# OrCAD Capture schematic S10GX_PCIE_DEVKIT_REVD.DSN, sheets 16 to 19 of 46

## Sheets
16 S10 GX Ground: size C
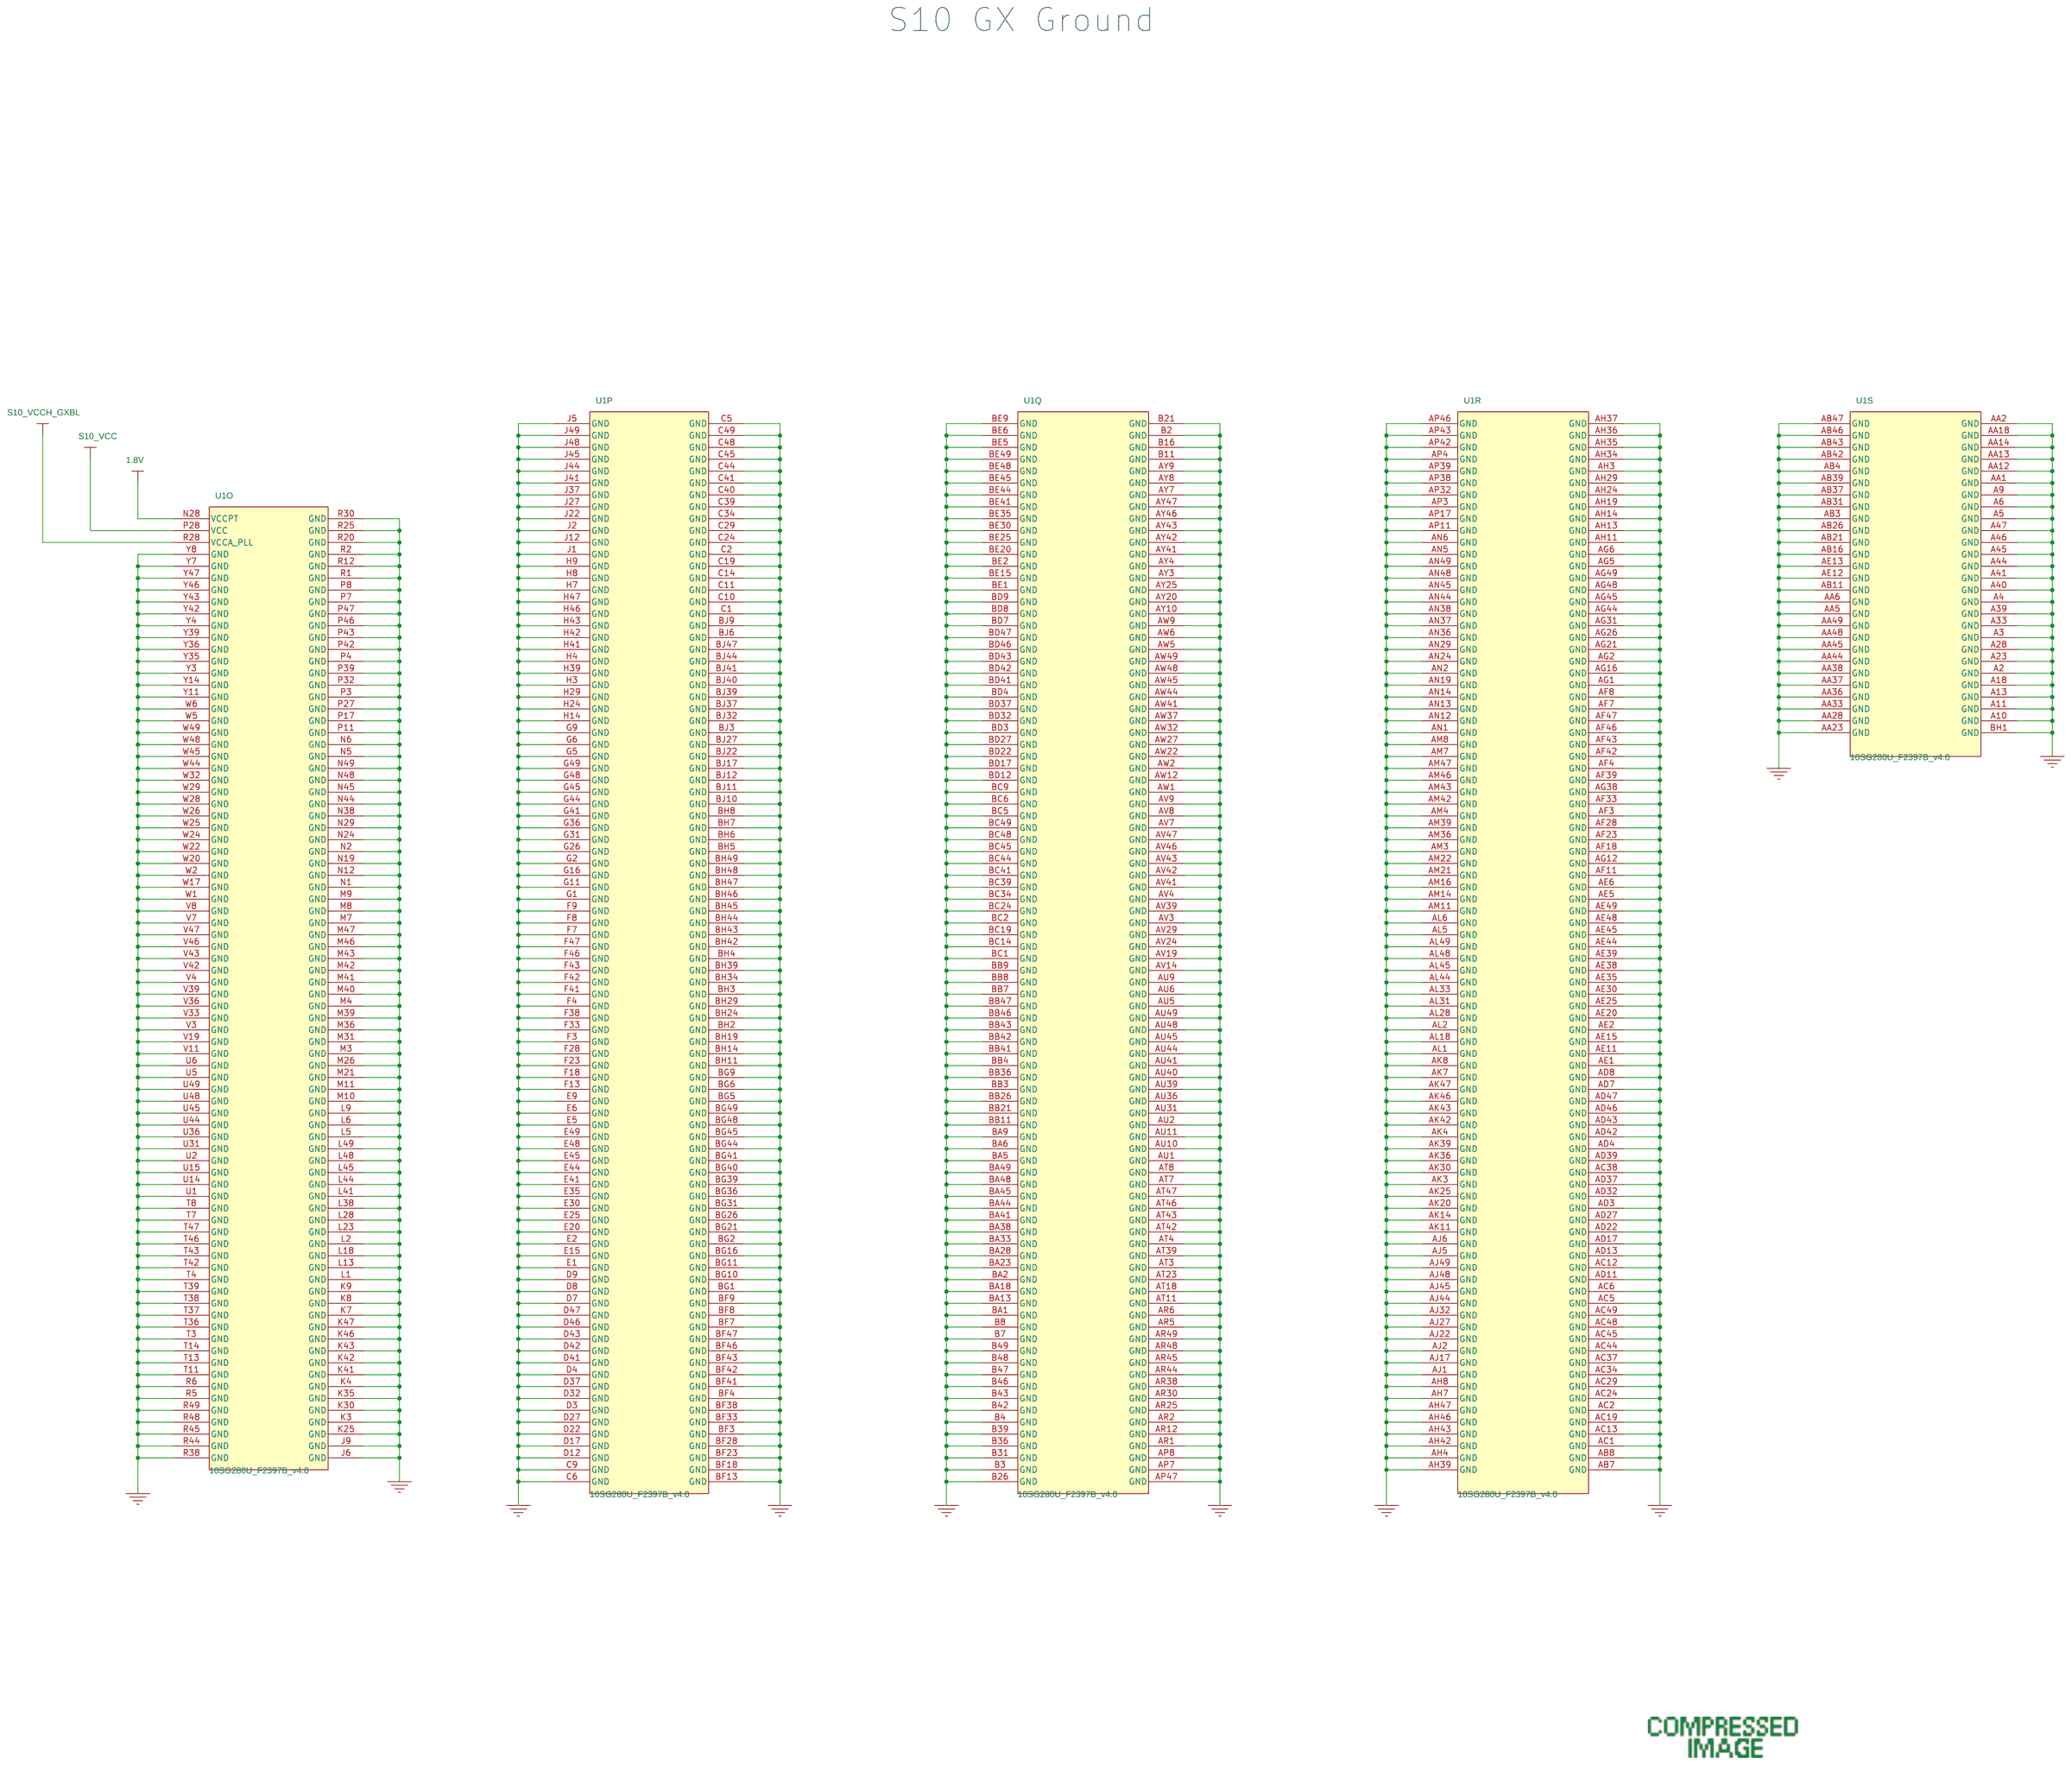
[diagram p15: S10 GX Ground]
17 PCIe Edge Gold Fingers: size C
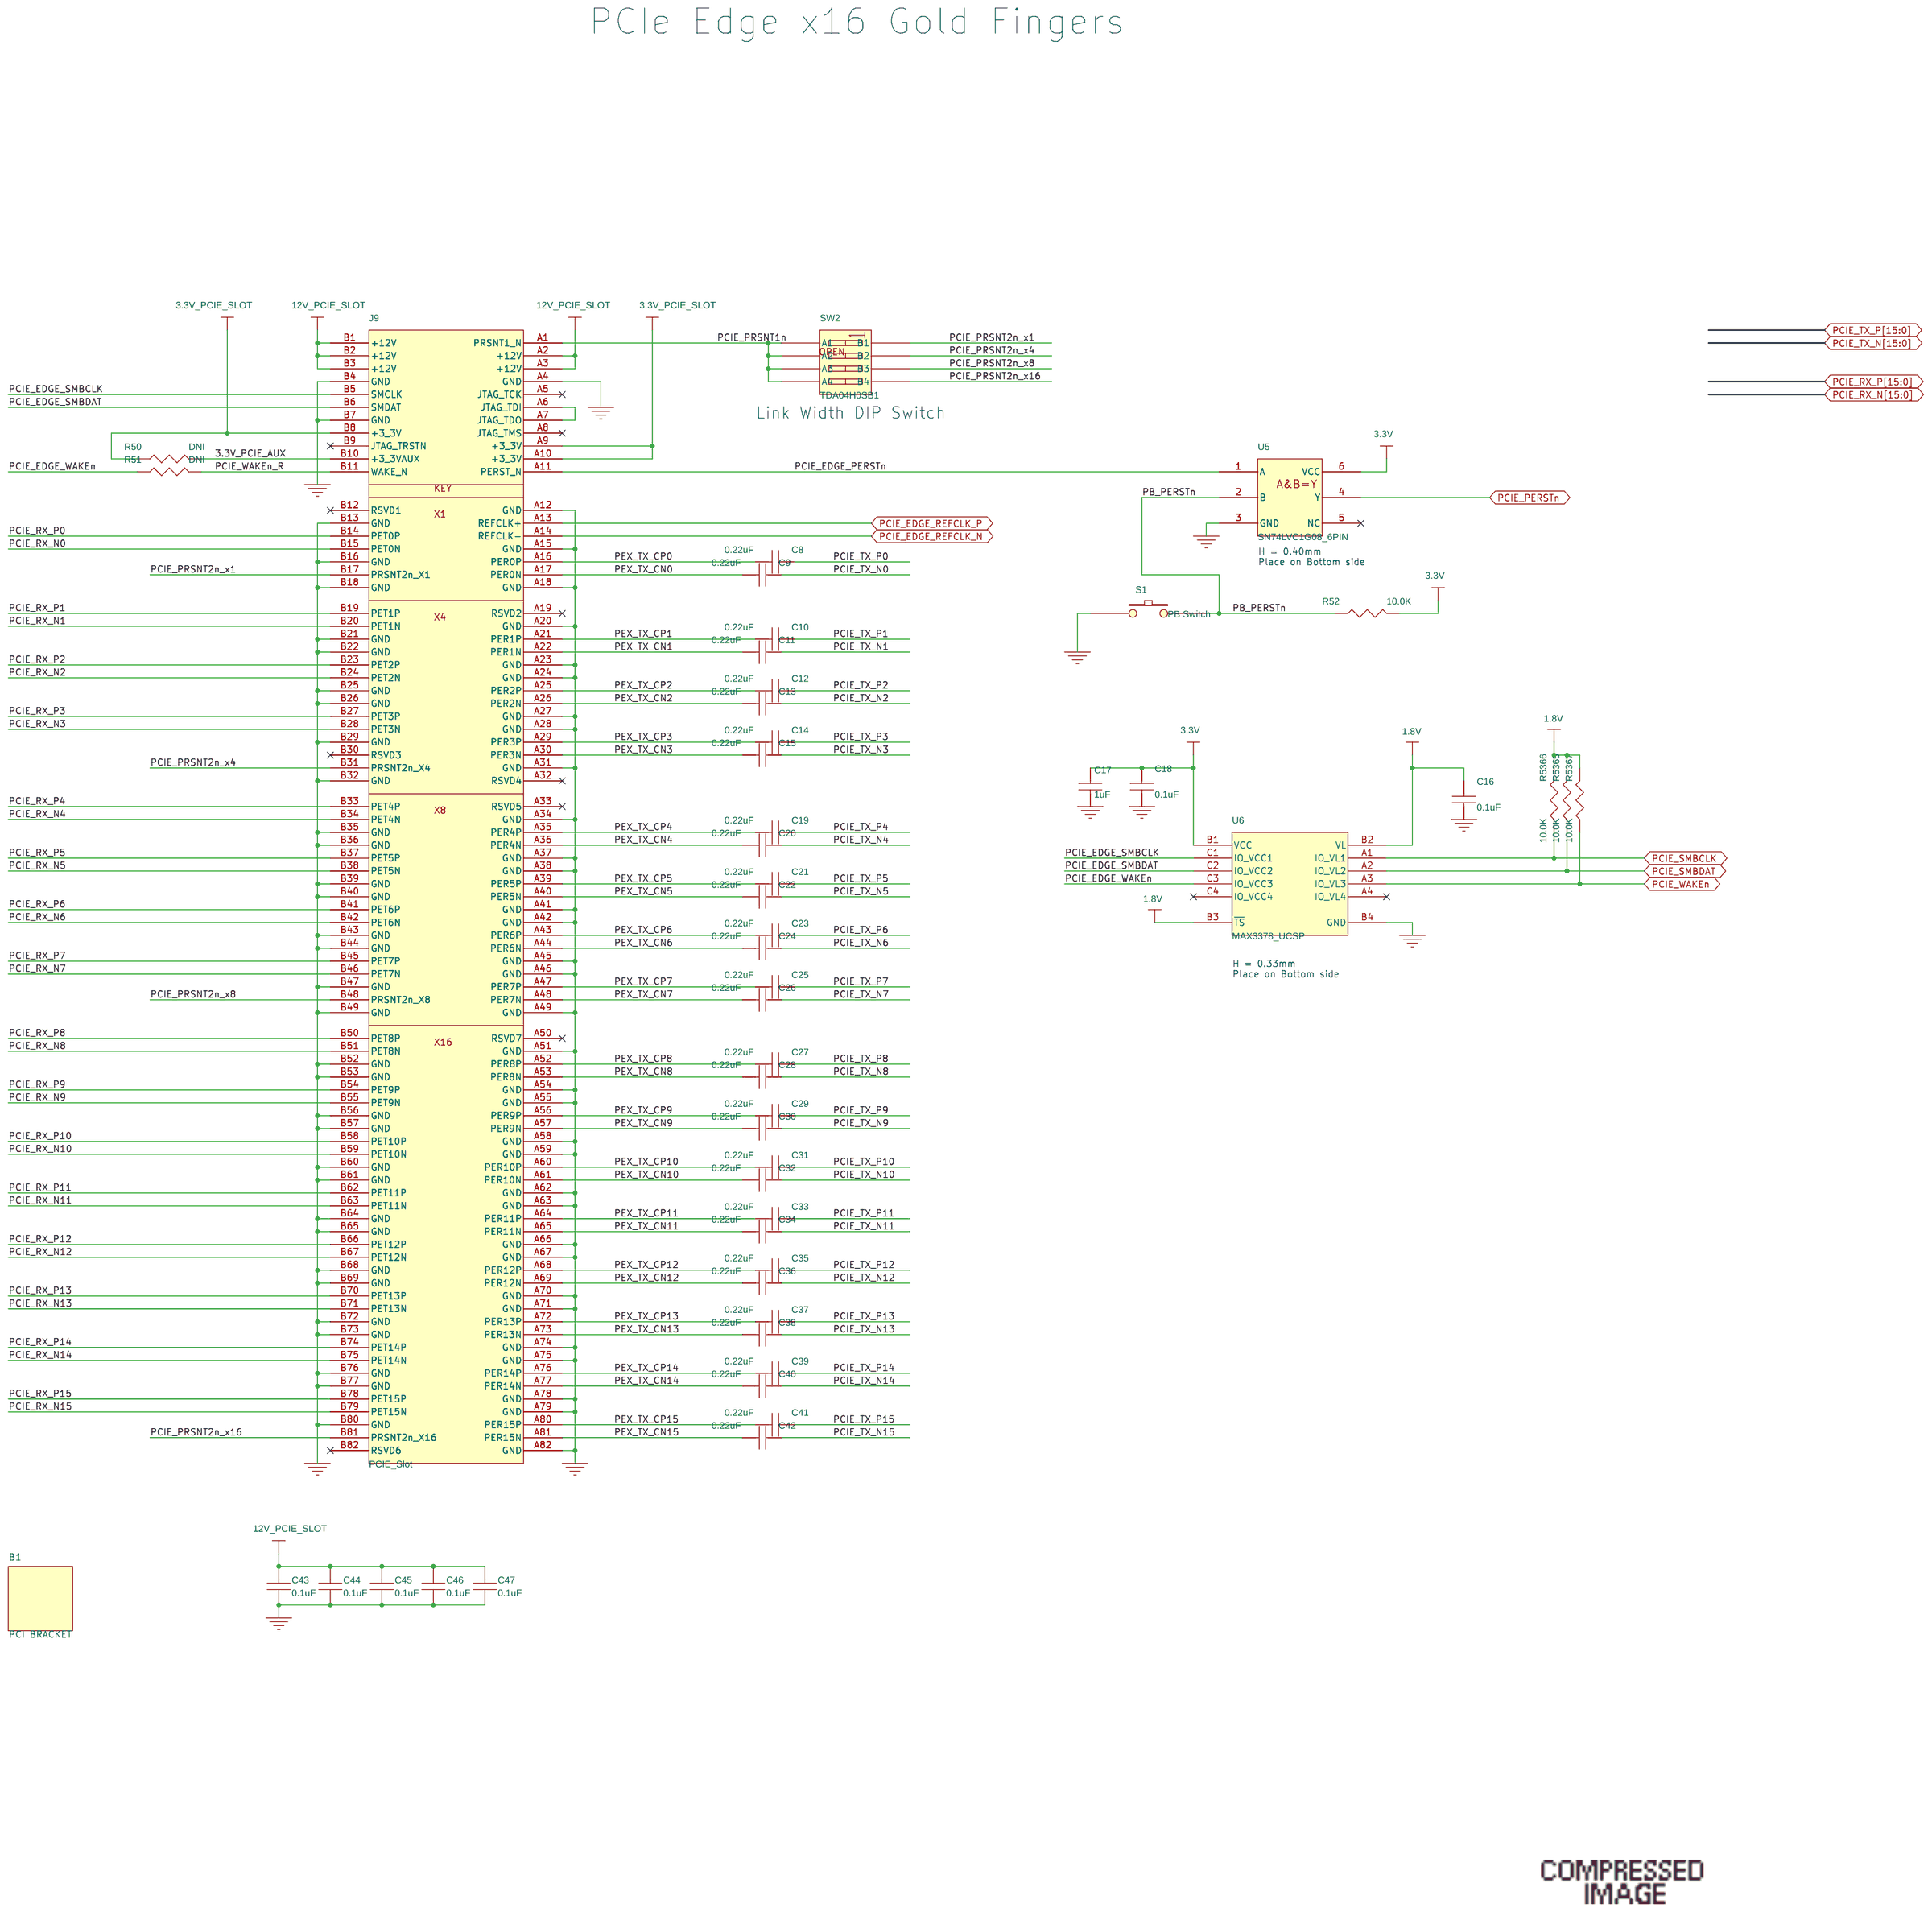
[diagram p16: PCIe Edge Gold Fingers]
18 Board System Clocks: size C
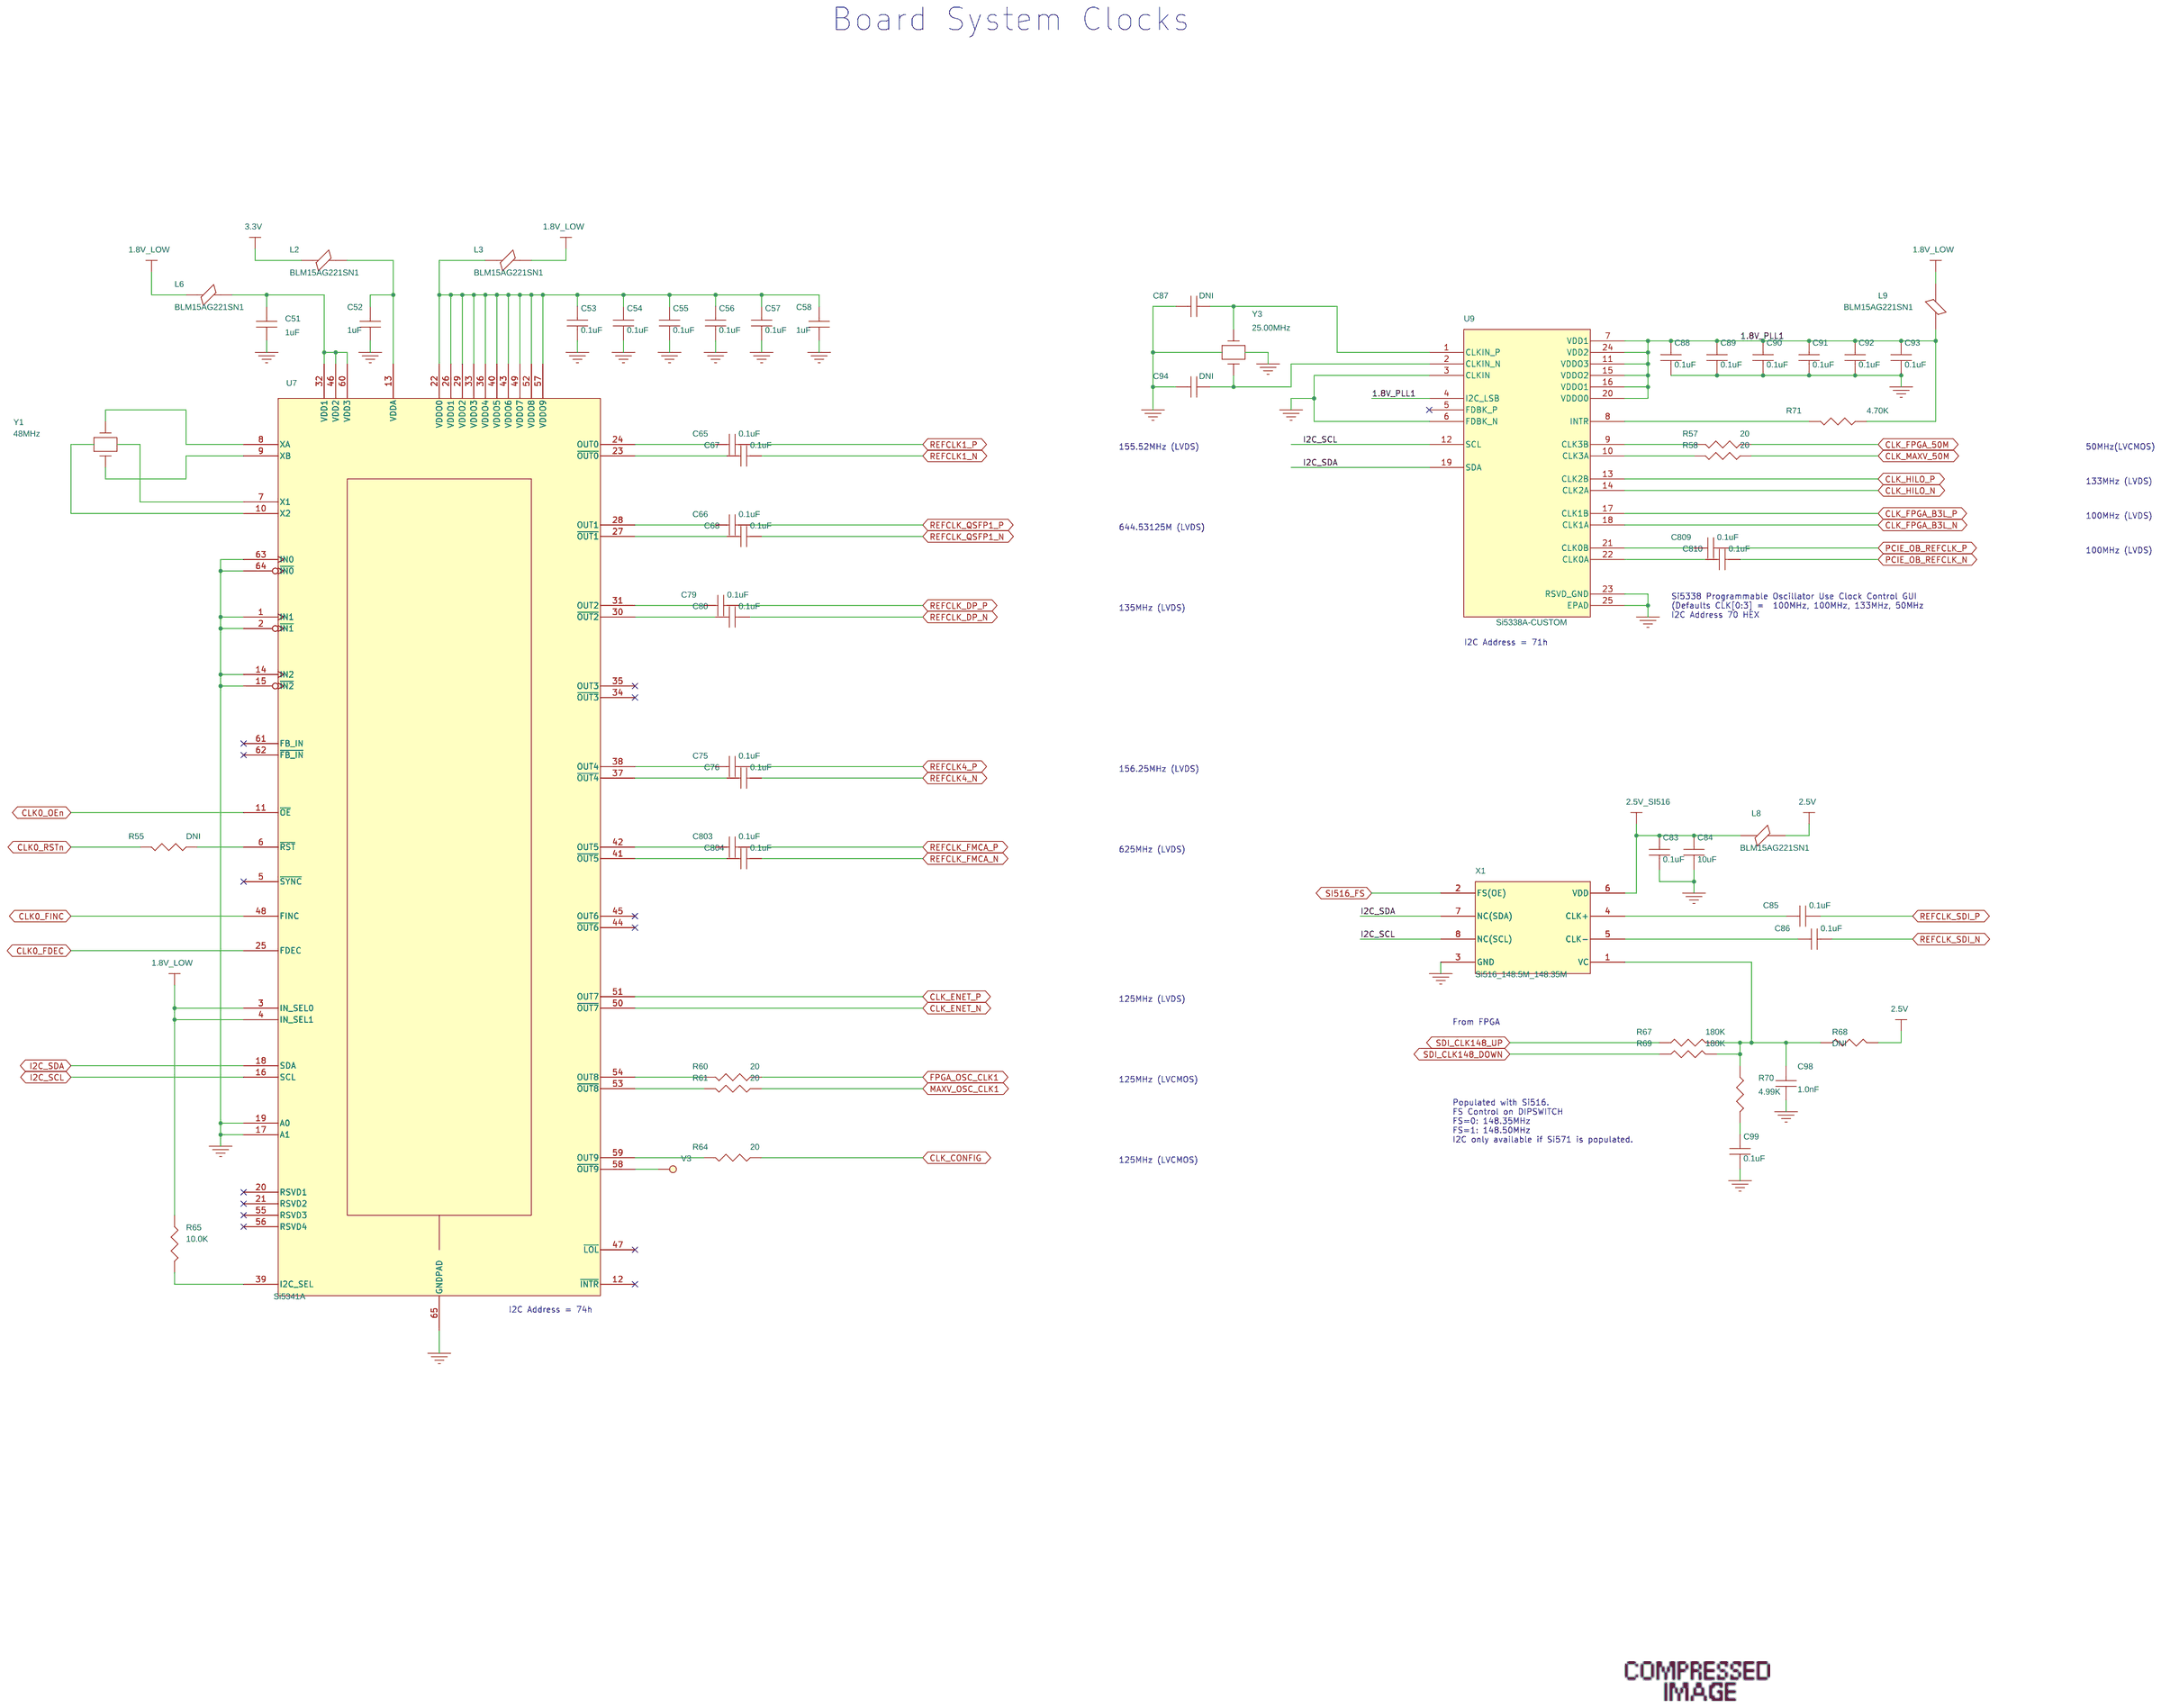
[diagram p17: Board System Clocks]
19 MaxV System Controller: size C
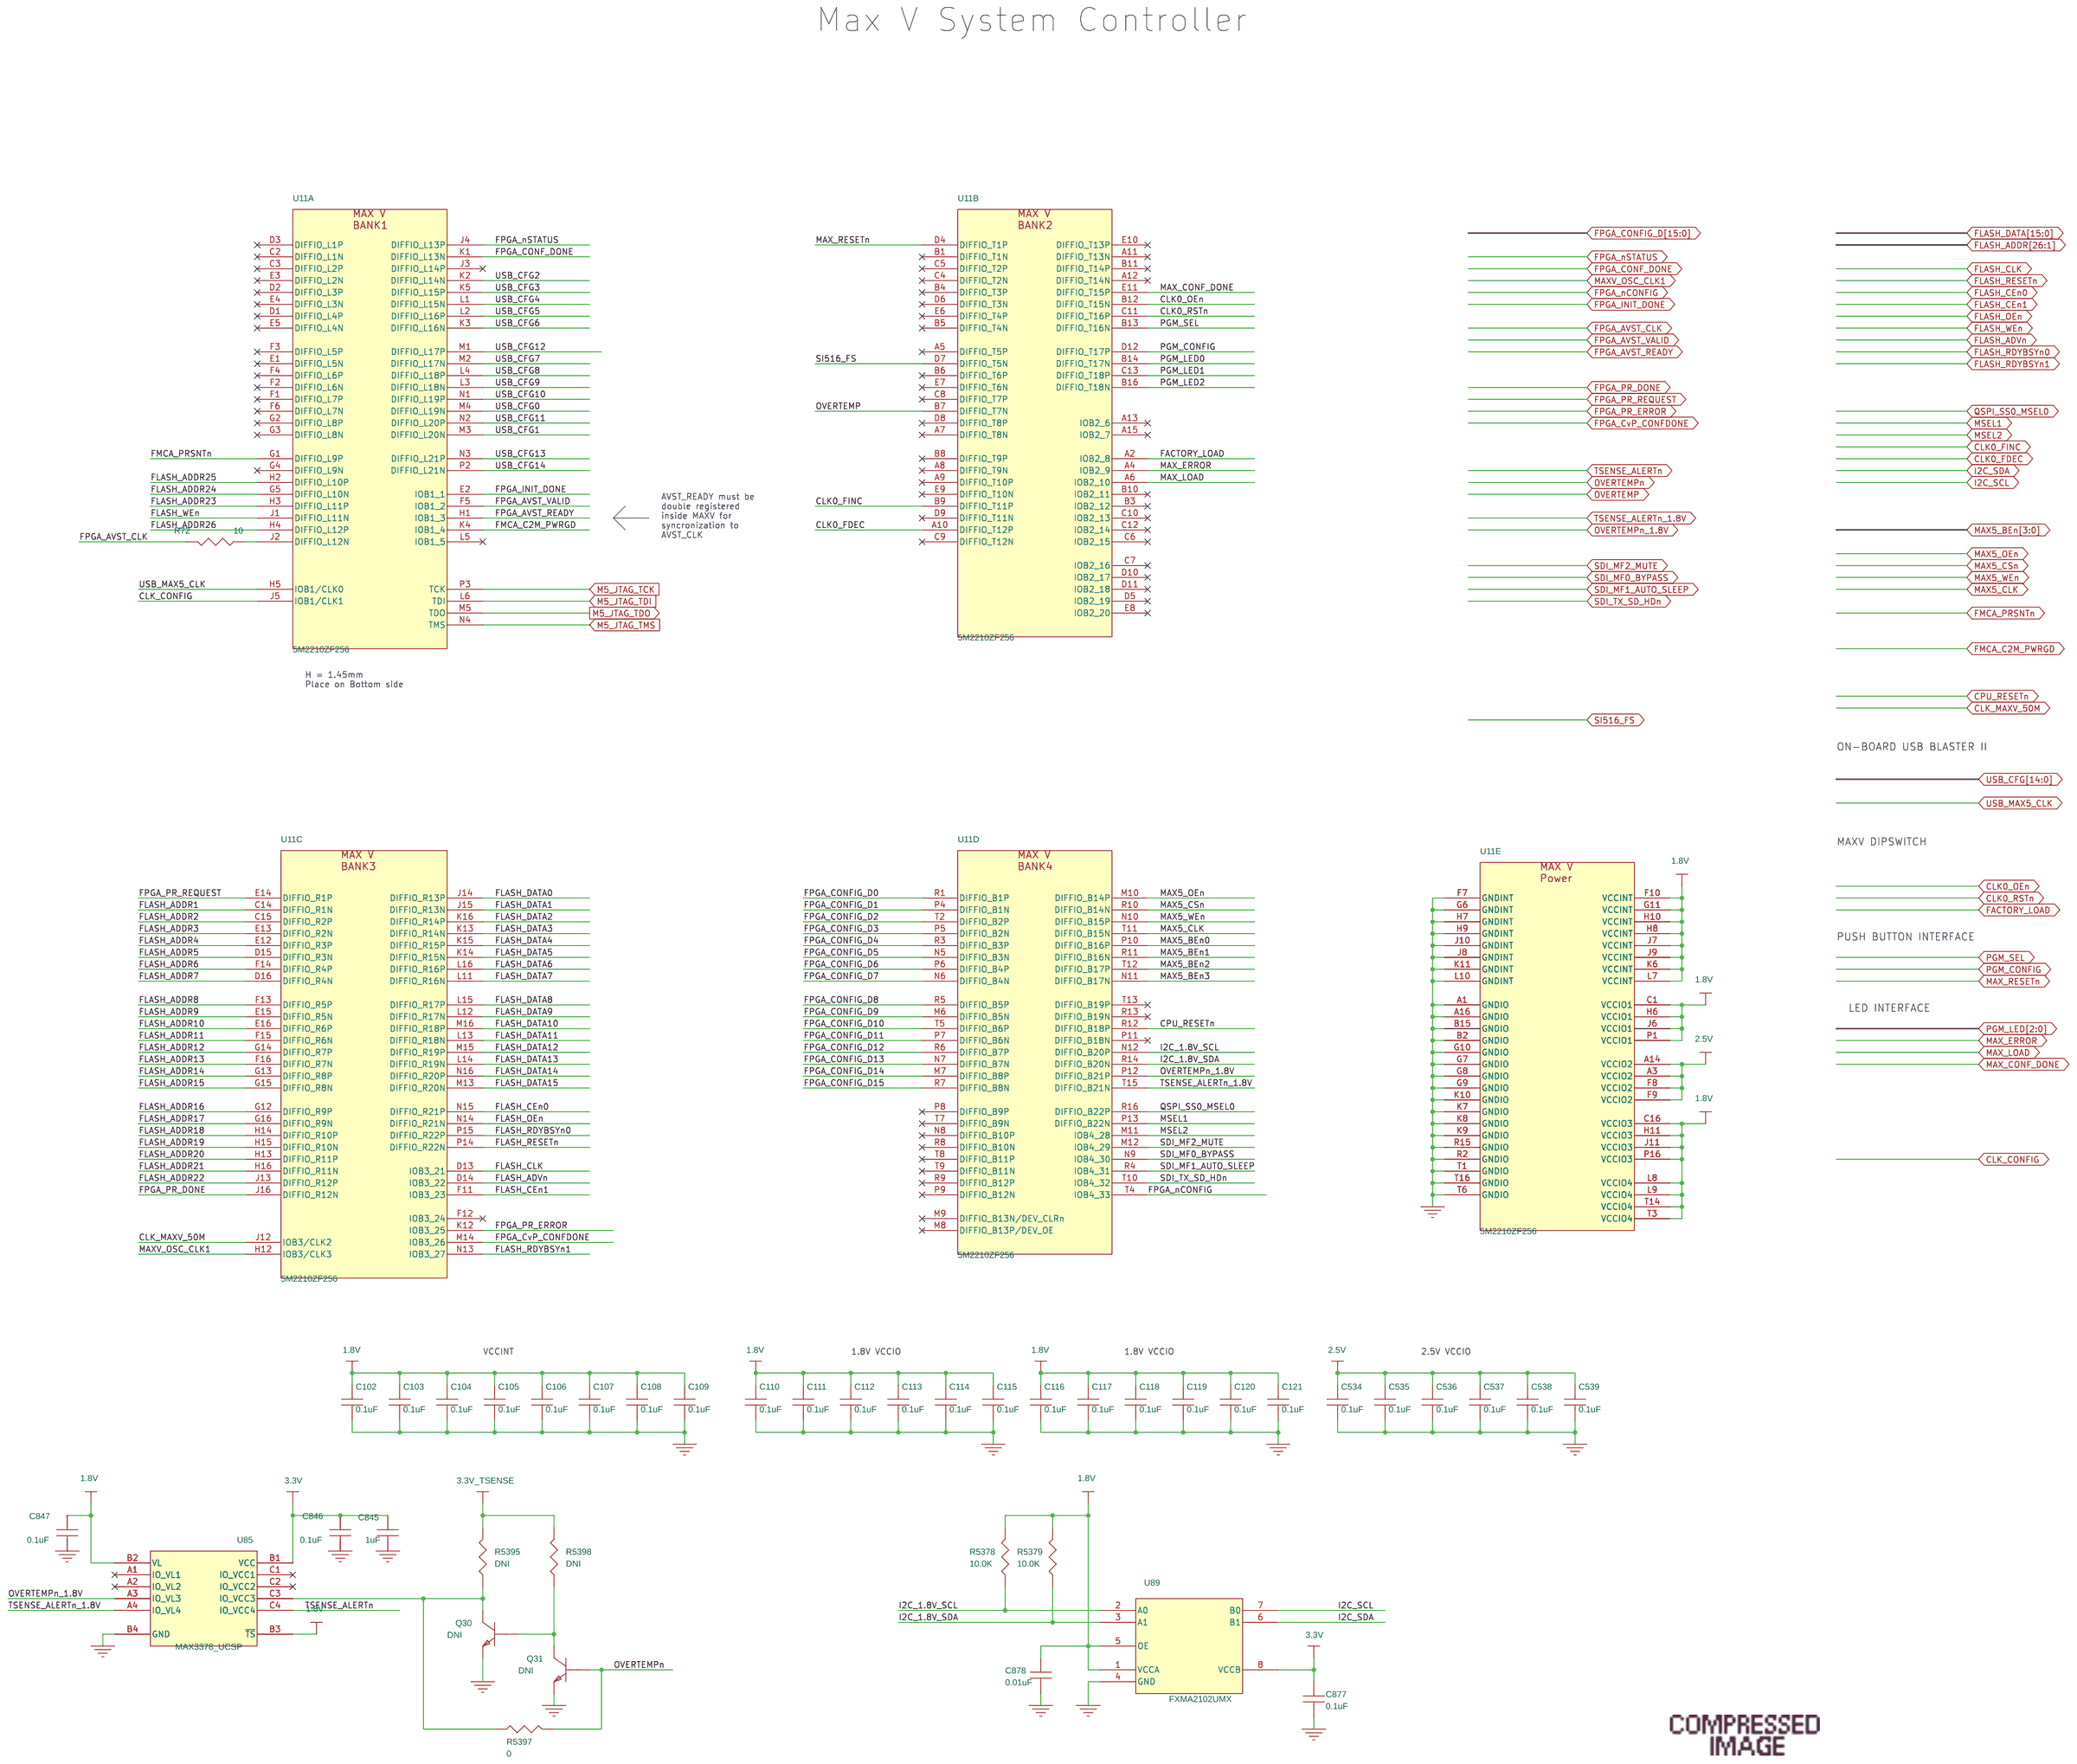
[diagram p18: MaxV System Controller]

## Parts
sheet Board System Clocks
C51  1uF  [0402]
C52  1uF  [0402]
C53  0.1uF  [0402]
C54  0.1uF  [0402]
C55  0.1uF  [0402]
C56  0.1uF  [0402]
C57  0.1uF  [0402]
C58  1uF  [0402]
C65  0.1uF  [0402]
C66  0.1uF  [0402]
C67  0.1uF  [0402]
C68  0.1uF  [0402]
C75  0.1uF  [0402]
C76  0.1uF  [0402]
C79  0.1uF  [0402]
C80  0.1uF  [0402]
C83  0.1uF  [0402]
C84  10uF  [0603]
C85  0.1uF  [0402]
C86  0.1uF  [0402]
C87  DNI  [0402]
C88  0.1uF  [0402]
C89  0.1uF  [0402]
C90  0.1uF  [0402]
C91  0.1uF  [0402]
C92  0.1uF  [0402]
C93  0.1uF  [0402]
C94  DNI  [0402]
C98  1.0nF  [0402]
C99  0.1uF  [0402]
C803  0.1uF  [0402]
C804  0.1uF  [0402]
C809  0.1uF  [0402]
C810  0.1uF  [0402]
L2  BLM15AG221SN1  [0402]
L3  BLM15AG221SN1  [0402]
L6  BLM15AG221SN1  [0402]
L8  BLM15AG221SN1  [0402]
L9  BLM15AG221SN1  [0402]
R55  DNI  [0402]
R57  20  [0402]
R58  20  [0402]
R60  20  [0402]
R61  20  [0402]
R64  20  [0402]
R65  10.0K  [0402]
R67  180K  [0402]
R68  DNI  [0402]
R69  180K  [0402]
R70  4.99K  [0402]
R71  4.70K  [0402]
U7  Si5341A  [QFN-64]
U9  Si5338A-CUSTOM  [QFN24]
V3  VIA_1  [TP_020RD_SMT]
X1  Si516_148.5M_148.35M  [XTAL_SI570]
Y1  48MHz  [XTAL_3mmx2mm]
Y3  25.00MHz  [XTAL_FA-128]
sheet MaxV System Controller
C102  0.1uF  [0402]
C103  0.1uF  [0402]
C104  0.1uF  [0402]
C105  0.1uF  [0402]
C106  0.1uF  [0402]
C107  0.1uF  [0402]
C108  0.1uF  [0402]
C109  0.1uF  [0402]
C110  0.1uF  [0402]
C111  0.1uF  [0402]
C112  0.1uF  [0402]
C113  0.1uF  [0402]
C114  0.1uF  [0402]
C115  0.1uF  [0402]
C116  0.1uF  [0402]
C117  0.1uF  [0402]
C118  0.1uF  [0402]
C119  0.1uF  [0402]
C120  0.1uF  [0402]
C121  0.1uF  [0402]
C534  0.1uF  [0402]
C535  0.1uF  [0402]
C536  0.1uF  [0402]
C537  0.1uF  [0402]
C538  0.1uF  [0402]
C539  0.1uF  [0402]
C845  1uF  [0402]
C846  0.1uF  [0402]
C847  0.1uF  [0402]
C877  0.1uF  [0402]
C878  0.01uF  [0402]
Q30  DNI  [SOT23_MMBT3904]
Q31  DNI  [SOT23_MMBT3904]
R72  10  [0402]
R5378  10.0K  [0402]
R5379  10.0K  [0402]
R5395  DNI  [0402]
R5397  0  [0402]
R5398  DNI  [0402]
U11  5M2210ZF256  [F256]  (sections A,B,C,D,E)
U85  MAX3378_UCSP  [UCSP-12]
U89  FXMA2102UMX  [UMLP]
sheet PCIe Edge Gold Fingers
B1  PCI BRACKET
C8  0.22uF  [0201]
C9  0.22uF  [0201]
C10  0.22uF  [0201]
C11  0.22uF  [0201]
C12  0.22uF  [0201]
C13  0.22uF  [0201]
C14  0.22uF  [0201]
C15  0.22uF  [0201]
C16  0.1uF  [0402]
C17  1uF  [0402]
C18  0.1uF  [0402]
C19  0.22uF  [0201]
C20  0.22uF  [0201]
C21  0.22uF  [0201]
C22  0.22uF  [0201]
C23  0.22uF  [0201]
C24  0.22uF  [0201]
C25  0.22uF  [0201]
C26  0.22uF  [0201]
C27  0.22uF  [0201]
C28  0.22uF  [0201]
C29  0.22uF  [0201]
C30  0.22uF  [0201]
C31  0.22uF  [0201]
C32  0.22uF  [0201]
C33  0.22uF  [0201]
C34  0.22uF  [0201]
C35  0.22uF  [0201]
C36  0.22uF  [0201]
C37  0.22uF  [0201]
C38  0.22uF  [0201]
C39  0.22uF  [0201]
C40  0.22uF  [0201]
C41  0.22uF  [0201]
C42  0.22uF  [0201]
C43  0.1uF  [0402]
C44  0.1uF  [0402]
C45  0.1uF  [0402]
C46  0.1uF  [0402]
C47  0.1uF  [0402]
J9  PCIE_Slot  [PCIX-16PORT]
R50  DNI  [0402]
R51  DNI  [0402]
R52  10.0K  [0402]
R5365  10.0K  [0402]
R5366  10.0K  [0402]
R5367  10.0K  [0402]
S1  PB Switch  [WURTH_6X3P5_TACT_SWITCH]
SW2  TDA04H0SB1  [DIPSWITCH_SMT_QUAD]
U5  SN74LVC1G08_6PIN  [PSON-6-DSF]
U6  MAX3378_UCSP  [UCSP-12]
sheet S10 GX Configuration
U1  10SG280U_F2397B_v4.0  [BGA_F2397B]  (sections A,B,C,D,E,F,G,H,I,J,K,L,M,N,O,P,Q,R,S)

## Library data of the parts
C17 C51 C52 C58 C845 = CAP: CAP - CER, 1uF, 10V, +/-10%, X5R, 0402; Item Num: P03-15479R; Lead Free Status: Yes; Manufacturer: Murata; Manufacturer Part Num: GRM155R61A105KE15D; Num Pins: 2; Part Class: CAPACITORS; RoHS Compliant: Yes
C43-C47 C53-C57 C65-C68 C75 C76 C79 C80 C83 C85 C86 C88-C93 C99 C803 C804 C809 C810 = CAP: CAP - CERAMIC,  0.1UF 0402 25VDC Y5V; AGILE_LINK: http://sj-agile9app/Agile/PLMServlet?action=OpenEmailObject&classid=10000&objid=213459527; Item Num: P03-15057R; LIFECYCLE_PHASE: Active; Lead Free Status: Lead Free; MFR_LIFECYCLE: Active; Manufacturer: Murata; Manufacturer Part Num: GRM155F51E104ZA01D; Num Pins: 2; PART_SUBCLASS: CAPACITORS; Part Class: CAPACITORS; RATED_VOLTAGE: 25V; RoHS Compliant: RoHS Compliant; TOLERANCE: +80%/-20%
C84 = CAP: CAP - CER 10UF 6.3V 20% X5R 0603; Item Num: P03-15733R; Lead Free Status: Lead Free; Manufacturer: Murata; Manufacturer Part Num: GRM188R60J106ME47X; Num Pins: 2; PART_SUBCLASS: CAPACITORS; Part Class: CAPACITORS; RoHS Compliant: RoHS Compliant
C87 C94 = CAP: CAP - CERAMIC, 18PF, 5%, 50V, 0402, NPO; AGILE_LINK: http://sj-agile9app/Agile/PLMServlet?action=OpenEmailObject&classid=10000&objid=213459014; Item Num: P03-15092R; Lead Free Status: Lead Free; MFR_LIFECYCLE: Active; Manufacturer: Panasonic; Manufacturer Part Num: ECJ-0EC1H180J; Num Pins: 2; PART_SUBCLASS: CAPACITORS; RoHS Compliant: Yes
C98 = CAP: CAP - CER, 1NF, 10%, 50V, X7R, 0402; AGILE_LINK: http://sj-agile9app/Agile/PLMServlet?action=OpenEmailObject&classid=10000&objid=256956561; Item Num: P03-15174R; LIFECYCLE_PHASE: Active; MFR_LIFECYCLE: Active; Manufacturer: Murata; Manufacturer Part Num: GRM155R71H102KA01D; Num Pins: 2; PART_SUBCLASS: CAPACITORS; RATED_VOLTAGE: 50V; RoHS Compliant: RoHS Compliant; TOLERANCE: +/-10%
L2 L3 L6 L8 L9 = BEAD_FERRITE_SM: IND - SMD EMI FILTERS/CHIP FERRITE BEAD, 220-OHM @ 100MHZ, 0.35-OHM DCR, 0402; Item Num: P04-16225R; LIFECYCLE_PHASE: Active; MFR_LIFECYCLE: Active; Manufacturer: Murata; Manufacturer Part Num: BLM15AG221SN1x; Num Pins: 2; PART_SUBCLASS: INDUCTORS
R55 = RESISTOR: RES ZERO OHM 1/16W 5% 0402 SMD; Altera Part No.: P02-14020R; Item Num: P02-14020R; Lead Free Status: No; Manufacturer: Panasonic; Manufacturer Part Num: ERJ-2GE0R00X; Num Pins: 2; Part Class: RESISTORS; Price: 0; RoHS Compliant: Yes; Tolerance: 5%
R57 R58 R60 R61 R64 = RESISTOR: RES - 20 OHM, 1/10W, 5%, 0402 SMD; Item Num: P02-17594R; Lead Free Status: Yes; Manufacturer: Panasonic; Manufacturer Part Num: ERJ-2GEJ200X; Num Pins: 2; Part Class: Resistors; Price: 0
R65 = RESISTOR: RES,10.0K OHMS,1.0%,1/16W, 0402; AGILE_LINK: http://sj-agile9app/Agile/PLMServlet?action=OpenEmailObject&classid=10000&objid=146548997; Item Num: P02-11364R; LIFECYCLE_PHASE: Active; Lead Free Status: No; MFR_LIFECYCLE: Active; Manufacturer: Panasonic; Manufacturer Part Num: ERJ-2RKF1002X; Num Pins: 2; PART_SUBCLASS: RESISTORS; POWER: 1/16W; RESISTANCE: 10K; RoHS Compliant: Yes; TOLERANCE: +/-1%
R67 R69 = RESISTOR: RES, 180 KOHM 1/16W 1% 0402 SMD; AGILE_LINK: http://sj-agile9app/Agile/PLMServlet?action=OpenEmailObject&classid=10000&objid=239318010; Item Num: P02-14144R; LIFECYCLE_PHASE: Active; MFR_LIFECYCLE: Active; Manufacturer: Yageo America/Phycomp; Manufacturer Part Num: RC0402FR-07180KL; Num Pins: 2; PACKAGING: Tape & Reel (TR); PART_SUBCLASS: RESISTORS; POWER: 1/16W; RoHS Compliant: RoHS Compliant; SUPPLIER_PART_NO: 311-180KLRCT-ND (DIGI-KEY); TOLERANCE: +/-1%
R68 = RESISTOR: RES,10.0K OHMS,1.0%,1/16W, 0402; AGILE_LINK: http://sj-agile9app/Agile/PLMServlet?action=OpenEmailObject&classid=10000&objid=146548997; Item Num: P02-11364R; LIFECYCLE_PHASE: Active; Lead Free Status: No; MFR_LIFECYCLE: Active; Manufacturer: Panasonic; Manufacturer Part Num: ERJ-2RKF1002X; Num Pins: 2; PART_SUBCLASS: RESISTORS; POWER: 1/16W; RESISTANCE: 10.0K; RoHS Compliant: Yes; TOLERANCE: +/-1%
R70 = RESISTOR: RES 4.99K OHM 1/16W 1% 0402 SMD; Item Num: P02-14129R; Lead Free Status: Yes; Manufacturer: Panasonic; Manufacturer Part Num: ERJ-2RKF4991X; Num Pins: 2; Part Class: Resistors; Price: 0
R71 = RESISTOR: RES,4.70K OHMS,1.0%,1/16W,0402; AGILE_LINK: http://sj-agile9app/Agile/PLMServlet?action=OpenEmailObject&classid=10000&objid=146753272; Item Num: P02-11384R; LIFECYCLE_PHASE: Active; Lead Free Status: No; MFR_LIFECYCLE: Active; Manufacturer: Vishay; Manufacturer Part Num: CRCW04024K70FKED; Num Pins: 2; PART_SUBCLASS: RESISTORS; POWER: 1/16W; RESISTANCE: 4.7K; RoHS Compliant: Yes; TOLERANCE: +/-1%
U7 = Si5341A: IC - S10 FPGA DEVKIT, PRE-PROGRAMMED U7 CLOCK DEVICE; Item Num: P01-18062R; Manufacturer: Silabs; Manufacturer Part Num: Si5341A-B05920-GM
U9 = Si5338A_0: IC - PROG, 1.8V LVDS QUAD CLOCK, 100MHz, 100MHz, 133MHz DEFAULTS, I2C 71h; Item Num: P01-18070R; Lead Free Status: Yes; MFR_LIFECYCLE: Active; Manufacturer: Silicon Labs; Manufacturer Part Num: Si5338A-B05923-GM; Num Pins: 25; Part Class: ICS; RoHS Compliant: YES
V3 = VIA_1
X1 = SI516_571: OSC - VCXO, FS1=148.50M/FS0=148.35M, TEMP +/-20PPM, TUNNING SLOPE 90PPM/V, VDD 2.5V, 5X7MM; Item Num: P13-27220R; Manufacturer: Silicon Laboratories; Manufacturer Part Num: 516FHA000132AAG
Y1 = CRYSTAL_SM_13: 48MHz ±10ppm Crystal 8pF 23 Ohm -40°C ~ 85°C AEC-Q200 Surface Mount 4-SMD, No Lead (DFN, LCC); Item Num: P07-19711R; Lead Free Status: Yes; MFR_LIFECYCLE: Active; Manufacturer: AVX Corp/Kyocera Corp; Manufacturer Part Num: CX3225SB48000D0FPJC1; Num Pins: 4; RoHS Compliant: Yes
Y3 = CRYSTAL_SM_13: CRYSTAL - MINI XTL, 25.00MHZ, FREQ +/-50PPM, RANGE +/-30PPM -20~70C, 18PF, 2.0MM X 1.6MM SMD; Item Num: P07-19688R; Lead Free Status: Yes; MFR_LIFECYCLE: Active; Manufacturer: Epson Toyocom; Manufacturer Part Num: FA-128 25.0000MB-C; Num Pins: 4; RoHS Compliant: Yes
C102-C121 C534-C539 = CAP: CAP - CERAMIC,  0.1UF 0402 25VDC Y5V; Dielectric: X5R; Item Num: P03-15057R; LIFECYCLE_PHASE: Active; Lead Free Status: Lead Free; Manufacturer: Murata; Manufacturer Part Num: GRM155F51E104ZA01D; Num Pins: 2; Part Class: CAPACITORS; Price: 0.07; RoHS Compliant: RoHS Compliant; Tolerance: +80%/-20%
C16 C18 C846 C847 = CAP: CAP - CERAMIC,  0.1UF 0402 25VDC Y5V; Dielectric: Y5V; Item Num: P03-15057R; LIFECYCLE_PHASE: Active; Lead Free Status: Lead Free; MFR_LIFECYCLE: Active; Manufacturer: Murata; Manufacturer Part Num: GRM155F51E104ZA01D; Num Pins: 2; PART_SUBCLASS: CAPACITORS; Part Class: CAPACITORS; RATED_VOLTAGE: 25V; RoHS Compliant: RoHS Compliant; Tolerance: +80%/-20%
C877 = CAP: CAP - CERAMIC,  0.1UF 0402 25VDC Y5V; Dielectric: Y5V; Item Num: P03-15057R; LIFECYCLE_PHASE: Active; Lead Free Status: Lead Free; MFR_LIFECYCLE: Active; Manufacturer: Murata; Manufacturer Part Num: GRM155F51E104ZA01D; Num Pins: 2; PART_SUBCLASS: CAPACITORS; Part Class: CAPACITORS; RATED_VOLTAGE: 25V; RoHS Compliant: RoHS Compliant; TOLERANCE: +80%/-20%
C878 = CAP: CAP, CER .01UF 16V X7R 0402; AGILE_LINK: http://sj-agile9app/Agile/PLMServlet?action=OpenEmailObject&classid=10000&objid=242850622; Item Num: P03-15137R; LIFECYCLE_PHASE: Active; MFR_LIFECYCLE: Active; Manufacturer: Murata; Manufacturer Part Num: GRM155R71C103KA01D; Num Pins: 2; PACKAGING: Tape & Reel (TR); PART_SUBCLASS: CAPACITORS; RATED_VOLTAGE: 16V; RoHS Compliant: RoHS Compliant; TOLERANCE: +/-10%
Q30 Q31 = 2N3904: TRANSISTOR -  NPN MMBT3904 SOT23; Item Num: P01-13004R; Manufacturer: Philips; Manufacturer Part Num: MMBT3904
R72 = RESISTOR: RES, 10 OHM, 1%, 1/16W, 0402; AGILE_LINK: http://sj-agile9app/Agile/PLMServlet?action=OpenEmailObject&classid=10000&objid=146932246; Item Num: P02-16268R; LIFECYCLE_PHASE: Active; MFR_LIFECYCLE: Active; Manufacturer: Panasonic; Manufacturer Part Num: ERJ-2RKF10R0X; Num Pins: 2; PART_SUBCLASS: RESISTORS; POWER: 1/16W; RoHS Compliant: RoHS Compliant; TOLERANCE: +/-1%
R5378 R5379 R5395 R5398 = RESISTOR: RES,10.0K OHMS,1.0%,1/16W, 0402; Item Num: P02-11364R; Lead Free Status: No; Manufacturer: Panasonic; Manufacturer Part Num: ERJ-2RKF1002X; Num Pins: 2; Part Class: Resistors; Price: 0
R5397 = RESISTOR: RES ZERO OHM 1/16W 5% 0402 SMD; Item Num: P02-14020R; Lead Free Status: No; Manufacturer: Panasonic; Manufacturer Part Num: ERJ-2GE0R00X; Num Pins: 2; Part Class: RESISTORS; RoHS Compliant: Yes
U11 = 5M2210ZF256_3: IC - Max V CPLD, 2210 LEs, 256FBGA 1.8V VCCINT; Item Num: P01-17326R; LIFECYCLE_PHASE: Preliminary; Lead Free Status: Lead Free; MFR_LIFECYCLE: Active; Manufacturer: Altera Corporation; Manufacturer Part Num: 5M2210ZF256C4N; Num Pins: 256; PART_SUBCLASS: ICS; RoHS Compliant: RoHS Compliant
U6 U85 = MAX3378_12UCSP: IC - QUAD LOW-VOLTAGE LEVEL TRANSLATOR, +/- 15KV, ESD-PROTECTED, 1UA, 8-16MBPS, 12-UCSP (1.5X2)MM; Item Num: P01-17875R; Lead Free Status: Yes; Manufacturer: Maxim Integrated Products, Inc.; Manufacturer Part Num: MAX3378EEBC+; Num Pins: 12; Part Class: ICs; RoHS Compliant: Yes
U89 = FXMA2102UMX: Dual Supply, 2-Bit Voltage Translator/Buffer/Repeater/Isolator for I2C application; Item Num: P01-17934R; Manufacturer: Fairchild
B1 = BLANK_PART: CUSTOM PCI BRACKET STRATIX 10 FPGA DEVKIT; Item Num: P12-27242R; Manufacturer: ???; Manufacturer Part Num: ???
C8-C15 C19-C42 = CAP: CAP - CER, 0.22UF, 10V, 10%, X5R, 0201; AGILE_LINK: http://sj-agile9app/Agile/PLMServlet?action=OpenEmailObject&classid=10000&objid=257560276; Item Num: P03-17614R; LIFECYCLE_PHASE: Active; Lead Free Status: Lead Free; MFR_LIFECYCLE: Active; Manufacturer: TDK Electronics; Manufacturer Part Num: C0603X5R1A224K; Num Pins: 2; PART_SUBCLASS: CAPACITORS; RATED_VOLTAGE: 10V; RoHS Compliant: RoHS Compliant; TOLERANCE: +/-10%
J9 = PCIE_Bracket_X16: Item Num: NA; Manufacturer: NA; Manufacturer's Part No.: NA
R50 R51 = RESISTOR: RES ZERO OHM 1/16W 5% 0402 SMD; Item Num: P02-14020R; Lead Free Status: No; Manufacturer: Panasonic; Manufacturer Part Num: ERJ-2GE0R00X; Num Pins: 2; Part Class: RESISTORS; Price: 0; RoHS Compliant: Yes
R52 R5365-R5367 = RESISTOR: RES,10.0K OHMS,1.0%,1/16W, 0402; AGILE_LINK: http://sj-agile9app/Agile/PLMServlet?action=OpenEmailObject&classid=10000&objid=146548997; Item Num: P02-11364R; LIFECYCLE_PHASE: Active; Lead Free Status: No; MFR_LIFECYCLE: Active; Manufacturer: Panasonic; Manufacturer Part Num: ERJ-2RKF1002X; Num Pins: 2; PART_SUBCLASS: RESISTORS; POWER: 1/16W; RoHS Compliant: Yes; TOLERANCE: +/-1%
S1 = TS-A02SA-2-S100_0: SWITCH - PUSH BUTTON 6.0X3.5MM SND; Item Num: P23-38485R; Lead Free Status: Yes; Manufacturer: Wurth Elektroniks; Manufacturer Part Num: 434121043816; Num Pins: 2; Part Class: Switches; RoHS Compliant: Yes
SW2 = SPST4: SWITCHES - 4 POS, 8 PIN, Ultra-mini SMT Half-pitch Slider DIP Switch; AGILE_LINK: http://sj-agile9app/Agile/PLMServlet?action=OpenEmailObject&classid=10000&objid=258073635; Item Num: P11-24098R; LIFECYCLE_PHASE: Preliminary; Lead Free Status: Not Lead Free; MFR_LIFECYCLE: Active; Manufacturer: C & K Components/ITT Industries; Num Pins: 8; PART_SUBCLASS: SWITCHES; RoHS Compliant: RoHS Compliant
U5 = SN74LVC1G08_6PIN: IC - SINGLE 2-INPUT POSITIVE-AND GATE, VCC 1.65-5.0V, DSF PACKAGE; Item Num: P01-17851R; Lead Free Status: Yes; Manufacturer: Texas Instruments; Manufacturer Part Num: SN74LVC1G08DSFR; Num Pins: 6; Part Class: ICs; RoHS Compliant: Yes
U1 = 10SG280U_F2397B_v4_1.0

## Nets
1.8V: C16.1 C102.1 C103.1 C104.1 C105.1 C106.1 C107.1 C108.1 C109.1 C110.1 C111.1 C112.1 C113.1 C114.1 C115.1 C116.1 C117.1 C118.1 C119.1 C120.1 C121.1 C847.1 C878.1 R5365.2 R5366.2 R5367.2 R5378.2 R5379.2 U1.N28(VCCPT) U6.B2(VL) U6.B3(~{TS}) U11.C1(VCCIO1) U11.C16(VCCIO3) U11.F10(VCCINT) U11.G11(VCCINT) U11.H6(VCCIO1) U11.H8(VCCINT) U11.H10(VCCINT) U11.H11(VCCIO3) U11.J6(VCCIO1) U11.J7(VCCINT) U11.J9(VCCINT) U11.J11(VCCIO3) U11.K6(VCCINT) U11.L7(VCCINT) U11.L8(VCCIO4) U11.L9(VCCIO4) U11.P1(VCCIO1) U11.P16(VCCIO3) U11.T3(VCCIO4) U11.T14(VCCIO4) U85.B2(VL) U85.B3(~{TS}) U89.1(VCCA) U89.5(OE) ; also on sheet 6 9 15 20 24 27 28 29 30 31 39 45
1.8V_LOW: L3.2 L6.1 L9.2 R65.1 U7.3(IN_SEL0) U7.4(IN_SEL1) ; also on sheet 39 46
1.8V_PLL1: C88.1 C89.1 C90.1 C91.1 C92.1 C93.1 L9.1 R71.2 U9.4(I2C_LSB) U9.7(VDD1) U9.11(VDDO3) U9.15(VDDO2) U9.16(VDDO1) U9.20(VDDO0) U9.24(VDD2)
2.5V: C534.1 C535.1 C536.1 C537.1 C538.1 C539.1 L8.2 R68.2 U11.A3(VCCIO2) U11.A14(VCCIO2) U11.F8(VCCIO2) U11.F9(VCCIO2) ; also on sheet 21 23 28 29 31 32 43 46
2.5V_Si516: C83.1 C84.1 L8.1 X1.6(VDD)
3.3V: C17.1 C18.1 C845.1 C846.1 C877.1 L2.1 R52.2 U5.6(VCC) U6.B1(VCC) U85.B1(VCC) U89.8(VCCB) ; also on sheet 9 23 24 25 27 28 29 30 32 34
3.3V_PCIE_AUX: J9.B10(+3_3VAUX) R50.2
3.3V_PCIE_SLOT: J9.A9(+3_3V) J9.A10(+3_3V) J9.B8(+3_3V) R50.1
3.3V_TSENSE: R5395.2 R5398.2 ; also on sheet 31 32
12V_PCIE_SLOT: C43.2 C44.2 C45.2 C46.2 C47.2 J9.A2(+12V) J9.A3(+12V) J9.B1(+12V) J9.B2(+12V) J9.B3(+12V) ; also on sheet 33
GND: C16.2 C17.2 C18.2 C43.1 C44.1 C45.1 C46.1 C47.1 C51.1 C52.1 C53.2 C54.2 C55.2 C56.2 C57.2 C58.1 C83.2 C84.2 C87.2 C88.2 C89.2 C90.2 C91.2 C92.2 C93.2 C94.2 C98.1 C99.2 C102.2 C103.2 C104.2 C105.2 C106.2 C107.2 C108.2 C109.2 C110.2 C111.2 C112.2 C113.2 C114.2 C115.2 C116.2 C117.2 C118.2 C119.2 C120.2 C121.2 C534.2 C535.2 C536.2 C537.2 C538.2 C539.2 C845.2 C846.2 C847.2 C877.2 C878.2 J9.A4(GND) J9.A12(GND) J9.A15(GND) J9.A18(GND) J9.A20(GND) J9.A23(GND) J9.A24(GND) J9.A27(GND) J9.A28(GND) J9.A31(GND) J9.A34(GND) J9.A37(GND) J9.A38(GND) J9.A41(GND) J9.A42(GND) J9.A45(GND) J9.A46(GND) J9.A49(GND) J9.A51(GND) J9.A54(GND) J9.A55(GND) J9.A58(GND) J9.A59(GND) J9.A62(GND) J9.A63(GND) J9.A66(GND) J9.A67(GND) J9.A70(GND) J9.A71(GND) J9.A74(GND) J9.A75(GND) J9.A78(GND) J9.A79(GND) J9.A82(GND) J9.B4(GND) J9.B7(GND) J9.B13(GND) J9.B16(GND) J9.B18(GND) J9.B21(GND) J9.B22(GND) J9.B25(GND) J9.B26(GND) J9.B29(GND) J9.B32(GND) J9.B35(GND) J9.B36(GND) J9.B39(GND) J9.B40(GND) J9.B43(GND) J9.B44(GND) J9.B47(GND) J9.B49(GND) J9.B52(GND) J9.B53(GND) J9.B56(GND) J9.B57(GND) J9.B60(GND) J9.B61(GND) J9.B64(GND) J9.B65(GND) J9.B68(GND) J9.B69(GND) J9.B72(GND) J9.B73(GND) J9.B76(GND) J9.B77(GND) J9.B80(GND) Q30.1(EMITTER) Q31.1(EMITTER) S1.1 U1.A2(GND) U1.A3(GND) U1.A4(GND) U1.A5(GND) U1.A6(GND) U1.A9(GND) U1.A10(GND) U1.A11(GND) U1.A13(GND) U1.A18(GND) U1.A23(GND) U1.A28(GND) U1.A33(GND) U1.A39(GND) U1.A40(GND) U1.A41(GND) U1.A44(GND) U1.A45(GND) U1.A46(GND) U1.A47(GND) U1.AA1(GND) U1.AA2(GND) U1.AA5(GND) U1.AA6(GND) U1.AA12(GND) U1.AA13(GND) U1.AA14(GND) U1.AA18(GND) U1.AA23(GND) U1.AA28(GND) U1.AA33(GND) U1.AA36(GND) U1.AA37(GND) U1.AA38(GND) U1.AA44(GND) U1.AA45(GND) U1.AA48(GND) U1.AA49(GND) U1.AB3(GND) U1.AB4(GND) U1.AB7(GND) U1.AB8(GND) U1.AB11(GND) U1.AB16(GND) U1.AB21(GND) U1.AB26(GND) U1.AB31(GND) U1.AB37(GND) U1.AB39(GND) U1.AB42(GND) U1.AB43(GND) U1.AB46(GND) U1.AB47(GND) U1.AC1(GND) U1.AC2(GND) U1.AC5(GND) U1.AC6(GND) U1.AC12(GND) U1.AC13(GND) U1.AC19(GND) U1.AC24(GND) U1.AC29(GND) U1.AC34(GND) U1.AC37(GND) U1.AC38(GND) U1.AC44(GND) U1.AC45(GND) U1.AC48(GND) U1.AC49(GND) U1.AD3(GND) U1.AD4(GND) U1.AD7(GND) U1.AD8(GND) U1.AD11(GND) U1.AD13(GND) U1.AD17(GND) U1.AD22(GND) U1.AD27(GND) U1.AD32(GND) U1.AD37(GND) U1.AD39(GND) U1.AD42(GND) U1.AD43(GND) U1.AD46(GND) U1.AD47(GND) U1.AE1(GND) U1.AE2(GND) U1.AE5(GND) U1.AE6(GND) U1.AE11(GND) U1.AE12(GND) U1.AE13(GND) U1.AE15(GND) U1.AE20(GND) U1.AE25(GND) U1.AE30(GND) U1.AE35(GND) U1.AE38(GND) U1.AE39(GND) U1.AE44(GND) U1.AE45(GND) U1.AE48(GND) U1.AE49(GND) U1.AF3(GND) U1.AF4(GND) U1.AF7(GND) U1.AF8(GND) U1.AF11(GND) U1.AF18(GND) U1.AF23(GND) U1.AF28(GND) U1.AF33(GND) U1.AF39(GND) U1.AF42(GND) U1.AF43(GND) U1.AF46(GND) U1.AF47(GND) U1.AG1(GND) U1.AG2(GND) U1.AG5(GND) U1.AG6(GND) U1.AG12(GND) U1.AG16(GND) U1.AG21(GND) U1.AG26(GND) U1.AG31(GND) U1.AG38(GND) U1.AG44(GND) U1.AG45(GND) U1.AG48(GND) U1.AG49(GND) U1.AH3(GND) U1.AH4(GND) U1.AH7(GND) U1.AH8(GND) U1.AH11(GND) U1.AH13(GND) U1.AH14(GND) U1.AH19(GND) U1.AH24(GND) U1.AH29(GND) U1.AH34(GND) U1.AH35(GND) U1.AH36(GND) U1.AH37(GND) U1.AH39(GND) U1.AH42(GND) U1.AH43(GND) U1.AH46(GND) U1.AH47(GND) U1.AJ1(GND) U1.AJ2(GND) U1.AJ5(GND) U1.AJ6(GND) U1.AJ17(GND) U1.AJ22(GND) U1.AJ27(GND) U1.AJ32(GND) U1.AJ44(GND) U1.AJ45(GND) U1.AJ48(GND) U1.AJ49(GND) U1.AK3(GND) U1.AK4(GND) U1.AK7(GND) U1.AK8(GND) U1.AK11(GND) U1.AK14(GND) U1.AK20(GND) U1.AK25(GND) U1.AK30(GND) U1.AK36(GND) U1.AK39(GND) U1.AK42(GND) U1.AK43(GND) U1.AK46(GND) U1.AK47(GND) U1.AL1(GND) U1.AL2(GND) U1.AL5(GND) U1.AL6(GND) U1.AL18(GND) U1.AL28(GND) U1.AL31(GND) U1.AL33(GND) U1.AL44(GND) U1.AL45(GND) U1.AL48(GND) U1.AL49(GND) U1.AM3(GND) U1.AM4(GND) U1.AM7(GND) U1.AM8(GND) U1.AM11(GND) U1.AM14(GND) U1.AM16(GND) U1.AM21(GND) U1.AM22(GND) U1.AM36(GND) U1.AM39(GND) U1.AM42(GND) U1.AM43(GND) U1.AM46(GND) U1.AM47(GND) U1.AN1(GND) U1.AN2(GND) U1.AN5(GND) U1.AN6(GND) U1.AN12(GND) U1.AN13(GND) U1.AN14(GND) U1.AN19(GND) U1.AN24(GND) U1.AN29(GND) U1.AN36(GND) U1.AN37(GND) U1.AN38(GND) U1.AN44(GND) U1.AN45(GND) U1.AN48(GND) U1.AN49(GND) U1.AP3(GND) U1.AP4(GND) U1.AP7(GND) U1.AP8(GND) U1.AP11(GND) U1.AP17(GND) U1.AP32(GND) U1.AP38(GND) U1.AP39(GND) U1.AP42(GND) U1.AP43(GND) U1.AP46(GND) U1.AP47(GND) U1.AR1(GND) U1.AR2(GND) U1.AR5(GND) U1.AR6(GND) U1.AR12(GND) U1.AR25(GND) U1.AR30(GND) U1.AR38(GND) U1.AR44(GND) U1.AR45(GND) U1.AR48(GND) U1.AR49(GND) U1.AT3(GND) U1.AT4(GND) U1.AT7(GND) U1.AT8(GND) U1.AT11(GND) U1.AT18(GND) U1.AT23(GND) U1.AT39(GND) U1.AT42(GND) U1.AT43(GND) U1.AT46(GND) U1.AT47(GND) U1.AU1(GND) U1.AU2(GND) U1.AU5(GND) U1.AU6(GND) U1.AU9(GND) U1.AU10(GND) U1.AU11(GND) U1.AU31(GND) U1.AU36(GND) U1.AU39(GND) U1.AU40(GND) U1.AU41(GND) U1.AU44(GND) U1.AU45(GND) U1.AU48(GND) U1.AU49(GND) U1.AV3(GND) U1.AV4(GND) U1.AV7(GND) U1.AV8(GND) U1.AV9(GND) U1.AV14(GND) U1.AV19(GND) U1.AV24(GND) U1.AV29(GND) U1.AV39(GND) U1.AV41(GND) U1.AV42(GND) U1.AV43(GND) U1.AV46(GND) U1.AV47(GND) U1.AW1(GND) U1.AW2(GND) U1.AW5(GND) U1.AW6(GND) U1.AW9(GND) U1.AW12(GND) U1.AW22(GND) U1.AW27(GND) U1.AW32(GND) U1.AW37(GND) U1.AW41(GND) U1.AW44(GND) U1.AW45(GND) U1.AW48(GND) U1.AW49(GND) U1.AY3(GND) U1.AY4(GND) U1.AY7(GND) U1.AY8(GND) U1.AY9(GND) U1.AY10(GND) U1.AY20(GND) U1.AY25(GND) U1.AY41(GND) U1.AY42(GND) U1.AY43(GND) U1.AY46(GND) U1.AY47(GND) U1.B2(GND) U1.B3(GND) U1.B4(GND) U1.B7(GND) U1.B8(GND) U1.B11(GND) U1.B16(GND) U1.B21(GND) U1.B26(GND) U1.B31(GND) U1.B36(GND) U1.B39(GND) U1.B42(GND) U1.B43(GND) U1.B46(GND) U1.B47(GND) U1.B48(GND) U1.B49(GND) U1.BA1(GND) U1.BA2(GND) U1.BA5(GND) U1.BA6(GND) U1.BA9(GND) U1.BA13(GND) U1.BA18(GND) U1.BA23(GND) U1.BA28(GND) U1.BA33(GND) U1.BA38(GND) U1.BA41(GND) U1.BA44(GND) U1.BA45(GND) U1.BA48(GND) U1.BA49(GND) U1.BB3(GND) U1.BB4(GND) U1.BB7(GND) U1.BB8(GND) U1.BB9(GND) U1.BB11(GND) U1.BB21(GND) U1.BB26(GND) U1.BB36(GND) U1.BB41(GND) U1.BB42(GND) U1.BB43(GND) U1.BB46(GND) U1.BB47(GND) U1.BC1(GND) U1.BC2(GND) U1.BC5(GND) U1.BC6(GND) U1.BC9(GND) U1.BC14(GND) U1.BC19(GND) U1.BC24(GND) U1.BC34(GND) U1.BC39(GND) U1.BC41(GND) U1.BC44(GND) U1.BC45(GND) U1.BC48(GND) U1.BC49(GND) U1.BD3(GND) U1.BD4(GND) U1.BD7(GND) U1.BD8(GND) U1.BD9(GND) U1.BD12(GND) U1.BD17(GND) U1.BD22(GND) U1.BD27(GND) U1.BD32(GND) U1.BD37(GND) U1.BD41(GND) U1.BD42(GND) U1.BD43(GND) U1.BD46(GND) U1.BD47(GND) U1.BE1(GND) U1.BE2(GND) U1.BE5(GND) U1.BE6(GND) U1.BE9(GND) U1.BE15(GND) U1.BE20(GND) U1.BE25(GND) U1.BE30(GND) U1.BE35(GND) U1.BE41(GND) U1.BE44(GND) U1.BE45(GND) U1.BE48(GND) U1.BE49(GND) U1.BF3(GND) U1.BF4(GND) U1.BF7(GND) U1.BF8(GND) U1.BF9(GND) U1.BF13(GND) U1.BF18(GND) U1.BF23(GND) U1.BF28(GND) U1.BF33(GND) U1.BF38(GND) U1.BF41(GND) U1.BF42(GND) U1.BF43(GND) U1.BF46(GND) U1.BF47(GND) U1.BG1(GND) U1.BG2(GND) U1.BG5(GND) U1.BG6(GND) U1.BG9(GND) U1.BG10(GND) U1.BG11(GND) U1.BG16(GND) U1.BG21(GND) U1.BG26(GND) U1.BG31(GND) U1.BG36(GND) U1.BG39(GND) U1.BG40(GND) U1.BG41(GND) U1.BG44(GND) U1.BG45(GND) U1.BG48(GND) U1.BG49(GND) U1.BH1(GND) U1.BH2(GND) U1.BH3(GND) U1.BH4(GND) U1.BH5(GND) U1.BH6(GND) U1.BH7(GND) U1.BH8(GND) U1.BH11(GND) U1.BH14(GND) U1.BH19(GND) U1.BH24(GND) U1.BH29(GND) U1.BH34(GND) U1.BH39(GND) U1.BH42(GND) U1.BH43(GND) U1.BH44(GND) U1.BH45(GND) U1.BH46(GND) U1.BH47(GND) U1.BH48(GND) U1.BH49(GND) U1.BJ3(GND) U1.BJ6(GND) U1.BJ9(GND) U1.BJ10(GND) U1.BJ11(GND) U1.BJ12(GND) U1.BJ17(GND) U1.BJ22(GND) U1.BJ27(GND) U1.BJ32(GND) U1.BJ37(GND) U1.BJ39(GND) U1.BJ40(GND) U1.BJ41(GND) U1.BJ44(GND) U1.BJ47(GND) U1.C1(GND) U1.C2(GND) U1.C5(GND) U1.C6(GND) U1.C9(GND) U1.C10(GND) U1.C11(GND) U1.C14(GND) U1.C19(GND) U1.C24(GND) U1.C29(GND) U1.C34(GND) U1.C39(GND) U1.C40(GND) U1.C41(GND) U1.C44(GND) U1.C45(GND) U1.C48(GND) U1.C49(GND) U1.D3(GND) U1.D4(GND) U1.D7(GND) U1.D8(GND) U1.D9(GND) U1.D12(GND) U1.D17(GND) U1.D22(GND) U1.D27(GND) U1.D32(GND) U1.D37(GND) U1.D41(GND) U1.D42(GND) U1.D43(GND) U1.D46(GND) U1.D47(GND) U1.E1(GND) U1.E2(GND) U1.E5(GND) U1.E6(GND) U1.E9(GND) U1.E15(GND) U1.E20(GND) U1.E25(GND) U1.E30(GND) U1.E35(GND) U1.E41(GND) U1.E44(GND) U1.E45(GND) U1.E48(GND) U1.E49(GND) U1.F3(GND) U1.F4(GND) U1.F7(GND) U1.F8(GND) U1.F9(GND) U1.F13(GND) U1.F18(GND) U1.F23(GND) U1.F28(GND) U1.F33(GND) U1.F38(GND) U1.F41(GND) U1.F42(GND) U1.F43(GND) U1.F46(GND) U1.F47(GND) U1.G1(GND) U1.G2(GND) U1.G5(GND) U1.G6(GND) U1.G9(GND) U1.G11(GND) U1.G16(GND) U1.G26(GND) U1.G31(GND) U1.G36(GND) U1.G41(GND) U1.G44(GND) U1.G45(GND) U1.G48(GND) U1.G49(GND) U1.H3(GND) U1.H4(GND) U1.H7(GND) U1.H8(GND) U1.H9(GND) U1.H14(GND) U1.H24(GND) U1.H29(GND) U1.H39(GND) U1.H41(GND) U1.H42(GND) U1.H43(GND) U1.H46(GND) U1.H47(GND) U1.J1(GND) U1.J2(GND) U1.J5(GND) U1.J6(GND) U1.J9(GND) U1.J12(GND) U1.J22(GND) U1.J27(GND) U1.J37(GND) U1.J41(GND) U1.J44(GND) U1.J45(GND) U1.J48(GND) U1.J49(GND) U1.K3(GND) U1.K4(GND) U1.K7(GND) U1.K8(GND) U1.K9(GND) U1.K25(GND) U1.K30(GND) U1.K35(GND) U1.K41(GND) U1.K42(GND) U1.K43(GND) U1.K46(GND) U1.K47(GND) U1.L1(GND) U1.L2(GND) U1.L5(GND) U1.L6(GND) U1.L9(GND) U1.L13(GND) U1.L18(GND) U1.L23(GND) U1.L28(GND) U1.L38(GND) U1.L41(GND) U1.L44(GND) U1.L45(GND) U1.L48(GND) U1.L49(GND) U1.M3(GND) U1.M4(GND) U1.M7(GND) U1.M8(GND) U1.M9(GND) U1.M10(GND) U1.M11(GND) U1.M21(GND) U1.M26(GND) U1.M31(GND) U1.M36(GND) U1.M39(GND) U1.M40(GND) U1.M41(GND) U1.M42(GND) U1.M43(GND) U1.M46(GND) U1.M47(GND) U1.N1(GND) U1.N2(GND) U1.N5(GND) U1.N6(GND) U1.N12(GND) U1.N19(GND) U1.N24(GND) U1.N29(GND) U1.N38(GND) U1.N44(GND) U1.N45(GND) U1.N48(GND) U1.N49(GND) U1.P3(GND) U1.P4(GND) U1.P7(GND) U1.P8(GND) U1.P11(GND) U1.P17(GND) U1.P27(GND) U1.P32(GND) U1.P39(GND) U1.P42(GND) U1.P43(GND) U1.P46(GND) U1.P47(GND) U1.R1(GND) U1.R2(GND) U1.R5(GND) U1.R6(GND) U1.R12(GND) U1.R20(GND) U1.R25(GND) U1.R30(GND) U1.R38(GND) U1.R44(GND) U1.R45(GND) U1.R48(GND) U1.R49(GND) U1.T3(GND) U1.T4(GND) U1.T7(GND) U1.T8(GND) U1.T11(GND) U1.T13(GND) U1.T14(GND) U1.T36(GND) U1.T37(GND) U1.T38(GND) U1.T39(GND) U1.T42(GND) U1.T43(GND) U1.T46(GND) U1.T47(GND) U1.U1(GND) U1.U2(GND) U1.U5(GND) U1.U6(GND) U1.U14(GND) U1.U15(GND) U1.U31(GND) U1.U36(GND) U1.U44(GND) U1.U45(GND) U1.U48(GND) U1.U49(GND) U1.V3(GND) U1.V4(GND) U1.V7(GND) U1.V8(GND) U1.V11(GND) U1.V19(GND) U1.V33(GND) U1.V36(GND) U1.V39(GND) U1.V42(GND) U1.V43(GND) U1.V46(GND) U1.V47(GND) U1.W1(GND) U1.W2(GND) U1.W5(GND) U1.W6(GND) U1.W17(GND) U1.W20(GND) U1.W22(GND) U1.W24(GND) U1.W25(GND) U1.W26(GND) U1.W28(GND) U1.W29(GND) U1.W32(GND) U1.W44(GND) U1.W45(GND) U1.W48(GND) U1.W49(GND) U1.Y3(GND) U1.Y4(GND) U1.Y7(GND) U1.Y8(GND) U1.Y11(GND) U1.Y14(GND) U1.Y35(GND) U1.Y36(GND) U1.Y39(GND) U1.Y42(GND) U1.Y43(GND) U1.Y46(GND) U1.Y47(GND) U5.3(GND) U6.B4(GND) U7.1(IN1) U7.2(~{IN1}) U7.14(IN2) U7.15(~{IN2}) U7.17(A1) U7.19(A0) U7.63(IN0) U7.64(~{IN0}) U7.65(GNDPAD) U9.3(CLKIN) U9.6(FDBK_N) U9.23(RSVD_GND) U9.25(EPAD) U11.A1(GNDIO) U11.A16(GNDIO) U11.B2(GNDIO) U11.B15(GNDIO) U11.F7(GNDINT) U11.G6(GNDINT) U11.G7(GNDIO) U11.G8(GNDIO) U11.G9(GNDIO) U11.G10(GNDIO) U11.H7(GNDINT) U11.H9(GNDINT) U11.J8(GNDINT) U11.J10(GNDINT) U11.K7(GNDIO) U11.K8(GNDIO) U11.K9(GNDIO) U11.K10(GNDIO) U11.K11(GNDINT) U11.L10(GNDINT) U11.R2(GNDIO) U11.R15(GNDIO) U11.T1(GNDIO) U11.T6(GNDIO) U11.T16(GNDIO) U85.B4(GND) U89.4(GND) X1.3(GND) Y3.2 Y3.4 ; also on sheet 6 7 8 9 10 11 12 13 14 15 20 21 23 24 25 27 28 29 30 31 32 33 34 35 36 37 38 39 40 41 42 43 44 45 46
CLK0_FDEC: U7.25(FDEC) U11.A10(DIFFIO_T12P)
CLK0_FINC: U7.48(FINC) U11.B9(DIFFIO_T11P)
CLK0_OEn: U7.11(~{OE}) U11.B12(DIFFIO_T15N) ; also on sheet 29
CLK0_RSTn: R55.2 U11.C11(DIFFIO_T16P) ; also on sheet 29
CLK_CONFIG: R64.1 U11.J5(IOB1/CLK1)
CLK_ENET_N: U7.50(~{OUT7}) ; also on sheet 8
CLK_ENET_P: U7.51(OUT7) ; also on sheet 8
CLK_FPGA_50M: R57.1 ; also on sheet 7
CLK_FPGA_B3L_N: U9.18(CLK1A) ; also on sheet 10
CLK_FPGA_B3L_P: U9.17(CLK1B) ; also on sheet 10
CLK_HILO_N: U9.14(CLK2A) ; also on sheet 8
CLK_HILO_P: U9.13(CLK2B) ; also on sheet 8
CLK_MAXV_50M: R58.1 U11.J12(IOB3/CLK2)
CPU_RESETn: U11.R12(DIFFIO_B18P) ; also on sheet 10 29
FACTORY_LOAD: U11.A2(IOB2_8) ; also on sheet 29
FLASH_ADDR1: U11.C14(DIFFIO_R1N) ; also on sheet 7 20
FLASH_ADDR2: U11.C15(DIFFIO_R2P) ; also on sheet 7 20
FLASH_ADDR3: U11.E13(DIFFIO_R2N) ; also on sheet 7 20
FLASH_ADDR4: U11.E12(DIFFIO_R3P) ; also on sheet 7 20
FLASH_ADDR5: U11.D15(DIFFIO_R3N) ; also on sheet 7 20
FLASH_ADDR6: U11.F14(DIFFIO_R4P) ; also on sheet 7 20
FLASH_ADDR7: U11.D16(DIFFIO_R4N) ; also on sheet 7 20
FLASH_ADDR8: U11.F13(DIFFIO_R5P) ; also on sheet 7 20
FLASH_ADDR9: U11.E15(DIFFIO_R5N) ; also on sheet 7 20
FLASH_ADDR10: U11.E16(DIFFIO_R6P) ; also on sheet 7 20
FLASH_ADDR11: U11.F15(DIFFIO_R6N) ; also on sheet 7 20
FLASH_ADDR12: U11.G14(DIFFIO_R7P) ; also on sheet 7 20
FLASH_ADDR13: U11.F16(DIFFIO_R7N) ; also on sheet 7 20
FLASH_ADDR14: U11.G13(DIFFIO_R8P) ; also on sheet 7 20
FLASH_ADDR15: U11.G15(DIFFIO_R8N) ; also on sheet 7 20
FLASH_ADDR16: U11.G12(DIFFIO_R9P) ; also on sheet 7 20
FLASH_ADDR17: U11.G16(DIFFIO_R9N) ; also on sheet 7 20
FLASH_ADDR18: U11.H14(DIFFIO_R10P) ; also on sheet 7 20
FLASH_ADDR19: U11.H15(DIFFIO_R10N) ; also on sheet 7 20
FLASH_ADDR20: U11.H13(DIFFIO_R11P) ; also on sheet 7 20
FLASH_ADDR21: U11.H16(DIFFIO_R11N) ; also on sheet 7 20
FLASH_ADDR22: U11.J13(DIFFIO_R12P) ; also on sheet 7 20
FLASH_ADDR23: U11.H3(DIFFIO_L11P) ; also on sheet 7 20
FLASH_ADDR24: U11.G5(DIFFIO_L10N) ; also on sheet 7 20
FLASH_ADDR25: U11.H2(DIFFIO_L10P) ; also on sheet 7 20
FLASH_ADDR26: U11.H4(DIFFIO_L12P) ; also on sheet 7 20
FLASH_ADVn: U11.D14(IOB3_22) ; also on sheet 7 20
FLASH_CEn0: U11.N15(DIFFIO_R21P) ; also on sheet 7 20
FLASH_CEn1: U11.F11(IOB3_23) ; also on sheet 7 20
FLASH_CLK: U11.D13(IOB3_21) ; also on sheet 7 20
FLASH_DATA0: U11.J14(DIFFIO_R13P) ; also on sheet 7 20
FLASH_DATA1: U11.J15(DIFFIO_R13N) ; also on sheet 7 20
FLASH_DATA2: U11.K16(DIFFIO_R14P) ; also on sheet 7 20
FLASH_DATA3: U11.K13(DIFFIO_R14N) ; also on sheet 7 20
FLASH_DATA4: U11.K15(DIFFIO_R15P) ; also on sheet 7 20
FLASH_DATA5: U11.K14(DIFFIO_R15N) ; also on sheet 7 20
FLASH_DATA6: U11.L16(DIFFIO_R16P) ; also on sheet 7 20
FLASH_DATA7: U11.L11(DIFFIO_R16N) ; also on sheet 7 20
FLASH_DATA8: U11.L15(DIFFIO_R17P) ; also on sheet 7 20
FLASH_DATA9: U11.L12(DIFFIO_R17N) ; also on sheet 7 20
FLASH_DATA10: U11.M16(DIFFIO_R18P) ; also on sheet 7 20
FLASH_DATA11: U11.L13(DIFFIO_R18N) ; also on sheet 7 20
FLASH_DATA12: U11.M15(DIFFIO_R19P) ; also on sheet 7 20
FLASH_DATA13: U11.L14(DIFFIO_R19N) ; also on sheet 7 20
FLASH_DATA14: U11.N16(DIFFIO_R20P) ; also on sheet 7 20
FLASH_DATA15: U11.M13(DIFFIO_R20N) ; also on sheet 7 20
FLASH_OEn: U11.N14(DIFFIO_R21N) ; also on sheet 7 20
FLASH_RDYBSYn0: U11.P15(DIFFIO_R22P) ; also on sheet 7 20
FLASH_RDYBSYn1: U11.N13(IOB3_27) ; also on sheet 7 20
FLASH_RESETn: U11.P14(DIFFIO_R22N) ; also on sheet 7 20
FLASH_WEn: U11.J1(DIFFIO_L11N) ; also on sheet 7 20
FMCA_C2M_PWRGD: U11.K4(IOB1_4) ; also on sheet 30
FMCA_PRSNTn: U11.G1(DIFFIO_L9P) ; also on sheet 10 25 29 30
FPGA_AVST_CLK: R72.2 ; also on sheet 9
FPGA_AVST_READY: U11.H1(IOB1_3) ; also on sheet 6
FPGA_AVST_VALID: U11.F5(IOB1_2) ; also on sheet 9
FPGA_CONF_DONE: U11.K1(DIFFIO_L13N) ; also on sheet 6
FPGA_CONFIG_D0: U11.R1(DIFFIO_B1P) ; also on sheet 9
FPGA_CONFIG_D1: U11.P4(DIFFIO_B1N) ; also on sheet 9
FPGA_CONFIG_D2: U11.T2(DIFFIO_B2P) ; also on sheet 9
FPGA_CONFIG_D3: U11.P5(DIFFIO_B2N) ; also on sheet 9
FPGA_CONFIG_D4: U11.R3(DIFFIO_B3P) ; also on sheet 9
FPGA_CONFIG_D5: U11.N5(DIFFIO_B3N) ; also on sheet 9
FPGA_CONFIG_D6: U11.P6(DIFFIO_B4P) ; also on sheet 9
FPGA_CONFIG_D7: U11.N6(DIFFIO_B4N) ; also on sheet 9
FPGA_CONFIG_D8: U11.R5(DIFFIO_B5P) ; also on sheet 9
FPGA_CONFIG_D9: U11.M6(DIFFIO_B5N) ; also on sheet 9
FPGA_CONFIG_D10: U11.T5(DIFFIO_B6P) ; also on sheet 9
FPGA_CONFIG_D11: U11.P7(DIFFIO_B6N) ; also on sheet 9
FPGA_CONFIG_D12: U11.R6(DIFFIO_B7P) ; also on sheet 9
FPGA_CONFIG_D13: U11.N7(DIFFIO_B7N) ; also on sheet 9
FPGA_CONFIG_D14: U11.M7(DIFFIO_B8P) ; also on sheet 9
FPGA_CONFIG_D15: U11.R7(DIFFIO_B8N) ; also on sheet 9
FPGA_CvP_CONFDONE: U11.M14(IOB3_26) ; also on sheet 6 9
FPGA_INIT_DONE: U11.E2(IOB1_1) ; also on sheet 6
FPGA_nCONFIG: U11.T4(IOB4_33) ; also on sheet 6
FPGA_nSTATUS: U11.J4(DIFFIO_L13P) ; also on sheet 6
FPGA_OSC_CLK1: R60.1 ; also on sheet 6
FPGA_PR_DONE: U11.J16(DIFFIO_R12N) ; also on sheet 9
FPGA_PR_ERROR: U11.K12(IOB3_25) ; also on sheet 9
FPGA_PR_REQUEST: U11.E14(DIFFIO_R1P) ; also on sheet 9
I2C_1.8V_SCL: R5378.1 U11.N12(DIFFIO_B20P) U89.2(A0)
I2C_1.8V_SDA: R5379.1 U11.R14(DIFFIO_B20N) U89.3(A1)
I2C_SCL: U7.16(SCL) U9.12(SCL) U89.7(B0) X1.8(NC(SCL)) ; also on sheet 29 31 32
I2C_SDA: U7.18(SDA) U9.19(SDA) U89.6(B1) X1.7(NC(SDA)) ; also on sheet 29 31 32
M5_JTAG_TCK: U11.P3(TCK) ; also on sheet 30
M5_JTAG_TDI: U11.L6(TDI) ; also on sheet 30
M5_JTAG_TDO: U11.M5(TDO) ; also on sheet 30
M5_JTAG_TMS: U11.N4(TMS) ; also on sheet 30
MAX5_BEn0: U11.P10(DIFFIO_B16P) ; also on sheet 7
MAX5_BEn1: U11.R11(DIFFIO_B16N) ; also on sheet 7
MAX5_BEn2: U11.T12(DIFFIO_B17P) ; also on sheet 7
MAX5_BEn3: U11.N11(DIFFIO_B17N) ; also on sheet 7
MAX5_CLK: U11.T11(DIFFIO_B15N) ; also on sheet 7
MAX5_CSn: U11.R10(DIFFIO_B14N) ; also on sheet 7
MAX5_OEn: U11.M10(DIFFIO_B14P) ; also on sheet 7
MAX5_WEn: U11.N10(DIFFIO_B15P) ; also on sheet 7
MAX_CONF_DONE: U11.E11(DIFFIO_T15P) ; also on sheet 29
MAX_ERROR: U11.A4(IOB2_9) ; also on sheet 29
MAX_LOAD: U11.A6(IOB2_10) ; also on sheet 29
MAX_RESETn: U11.D4(DIFFIO_T1P) ; also on sheet 29
MAXV_OSC_CLK1: R61.1 U11.H12(IOB3/CLK3)
MSEL1: U11.P13(DIFFIO_B22N) ; also on sheet 6
MSEL2: U11.M11(IOB4_28) ; also on sheet 6
OVERTEMP: U11.B7(DIFFIO_T7N) ; also on sheet 32
OVERTEMPn: Q31.2(BASE) R5397.2 ; also on sheet 31 32
OVERTEMPn_1.8V: U11.P12(DIFFIO_B21P) U85.A3(IO_VL3) ; also on sheet 10
PB_PERSTn: R52.1 S1.2 U5.2(B)
PCIE_EDGE_PERSTn: J9.A11(PERST_N) U5.1(A)
PCIE_EDGE_REFCLK_N: J9.A14(REFCLK-) ; also on sheet 11
PCIE_EDGE_REFCLK_P: J9.A13(REFCLK+) ; also on sheet 11
PCIE_EDGE_SMBCLK: J9.B5(SMCLK) U6.C1(IO_VCC1)
PCIE_EDGE_SMBDAT: J9.B6(SMDAT) U6.C2(IO_VCC2)
PCIE_EDGE_WAKEn: R51.1 U6.C3(IO_VCC3)
PCIE_OB_REFCLK_N: C810.2 ; also on sheet 11
PCIE_OB_REFCLK_P: C809.2 ; also on sheet 11
PCIE_PERSTn: U5.4(Y) ; also on sheet 6
PCIE_PRSNT1n: J9.A1(PRSNT1_N) SW2.1(A1) SW2.2(A2) SW2.3(A3) SW2.4(A4)
PCIE_PRSNT2n_x1: J9.B17(PRSNT2n_X1) SW2.8(B1)
PCIE_PRSNT2n_x4: J9.B31(PRSNT2n_X4) SW2.7(B2)
PCIE_PRSNT2n_x8: J9.B48(PRSNT2n_X8) SW2.6(B3)
PCIE_PRSNT2n_x16: J9.B81(PRSNT2n_X16) SW2.5(B4)
PCIE_RX_N0: J9.B15(PET0N) ; also on sheet 11
PCIE_RX_N1: J9.B20(PET1N) ; also on sheet 11
PCIE_RX_N2: J9.B24(PET2N) ; also on sheet 11
PCIE_RX_N3: J9.B28(PET3N) ; also on sheet 11
PCIE_RX_N4: J9.B34(PET4N) ; also on sheet 11
PCIE_RX_N5: J9.B38(PET5N) ; also on sheet 11
PCIE_RX_N6: J9.B42(PET6N) ; also on sheet 11
PCIE_RX_N7: J9.B46(PET7N) ; also on sheet 11
PCIE_RX_N8: J9.B51(PET8N) ; also on sheet 11
PCIE_RX_N9: J9.B55(PET9N) ; also on sheet 11
PCIE_RX_N10: J9.B59(PET10N) ; also on sheet 11
PCIE_RX_N11: J9.B63(PET11N) ; also on sheet 11
PCIE_RX_N12: J9.B67(PET12N) ; also on sheet 11
PCIE_RX_N13: J9.B71(PET13N) ; also on sheet 11
PCIE_RX_N14: J9.B75(PET14N) ; also on sheet 11
PCIE_RX_N15: J9.B79(PET15N) ; also on sheet 11
PCIE_RX_P0: J9.B14(PET0P) ; also on sheet 11
PCIE_RX_P1: J9.B19(PET1P) ; also on sheet 11
PCIE_RX_P2: J9.B23(PET2P) ; also on sheet 11
PCIE_RX_P3: J9.B27(PET3P) ; also on sheet 11
PCIE_RX_P4: J9.B33(PET4P) ; also on sheet 11
PCIE_RX_P5: J9.B37(PET5P) ; also on sheet 11
PCIE_RX_P6: J9.B41(PET6P) ; also on sheet 11
PCIE_RX_P7: J9.B45(PET7P) ; also on sheet 11
PCIE_RX_P8: J9.B50(PET8P) ; also on sheet 11
PCIE_RX_P9: J9.B54(PET9P) ; also on sheet 11
PCIE_RX_P10: J9.B58(PET10P) ; also on sheet 11
PCIE_RX_P11: J9.B62(PET11P) ; also on sheet 11
PCIE_RX_P12: J9.B66(PET12P) ; also on sheet 11
PCIE_RX_P13: J9.B70(PET13P) ; also on sheet 11
PCIE_RX_P14: J9.B74(PET14P) ; also on sheet 11
PCIE_RX_P15: J9.B78(PET15P) ; also on sheet 11
PCIE_SMBCLK: R5366.1 U6.A1(IO_VL1) ; also on sheet 7
PCIE_SMBDAT: R5365.1 U6.A2(IO_VL2) ; also on sheet 7
PCIE_TX_N0: C9.1 ; also on sheet 11
PCIE_TX_N1: C11.1 ; also on sheet 11
PCIE_TX_N2: C13.1 ; also on sheet 11
PCIE_TX_N3: C15.1 ; also on sheet 11
PCIE_TX_N4: C20.1 ; also on sheet 11
PCIE_TX_N5: C22.1 ; also on sheet 11
PCIE_TX_N6: C24.1 ; also on sheet 11
PCIE_TX_N7: C26.1 ; also on sheet 11
PCIE_TX_N8: C28.1 ; also on sheet 11
PCIE_TX_N9: C30.1 ; also on sheet 11
PCIE_TX_N10: C32.1 ; also on sheet 11
PCIE_TX_N11: C34.1 ; also on sheet 11
PCIE_TX_N12: C36.1 ; also on sheet 11
PCIE_TX_N13: C38.1 ; also on sheet 11
PCIE_TX_N14: C40.1 ; also on sheet 11
PCIE_TX_N15: C42.1 ; also on sheet 11
PCIE_TX_P0: C8.1 ; also on sheet 11
PCIE_TX_P1: C10.1 ; also on sheet 11
PCIE_TX_P2: C12.1 ; also on sheet 11
PCIE_TX_P3: C14.1 ; also on sheet 11
PCIE_TX_P4: C19.1 ; also on sheet 11
PCIE_TX_P5: C21.1 ; also on sheet 11
PCIE_TX_P6: C23.1 ; also on sheet 11
PCIE_TX_P7: C25.1 ; also on sheet 11
PCIE_TX_P8: C27.1 ; also on sheet 11
PCIE_TX_P9: C29.1 ; also on sheet 11
PCIE_TX_P10: C31.1 ; also on sheet 11
PCIE_TX_P11: C33.1 ; also on sheet 11
PCIE_TX_P12: C35.1 ; also on sheet 11
PCIE_TX_P13: C37.1 ; also on sheet 11
PCIE_TX_P14: C39.1 ; also on sheet 11
PCIE_TX_P15: C41.1 ; also on sheet 11
PCIE_WAKEn: R5367.1 U6.A3(IO_VL3) ; also on sheet 7
PCIE_WAKEn_R: J9.B11(WAKE_N) R51.2
PEX_TX_CN0: C9.2 J9.A17(PER0N)
PEX_TX_CN1: C11.2 J9.A22(PER1N)
PEX_TX_CN2: C13.2 J9.A26(PER2N)
PEX_TX_CN3: C15.2 J9.A30(PER3N)
PEX_TX_CN4: C20.2 J9.A36(PER4N)
PEX_TX_CN5: C22.2 J9.A40(PER5N)
PEX_TX_CN6: C24.2 J9.A44(PER6N)
PEX_TX_CN7: C26.2 J9.A48(PER7N)
PEX_TX_CN8: C28.2 J9.A53(PER8N)
PEX_TX_CN9: C30.2 J9.A57(PER9N)
PEX_TX_CN10: C32.2 J9.A61(PER10N)
PEX_TX_CN11: C34.2 J9.A65(PER11N)
PEX_TX_CN12: C36.2 J9.A69(PER12N)
PEX_TX_CN13: C38.2 J9.A73(PER13N)
PEX_TX_CN14: C40.2 J9.A77(PER14N)
PEX_TX_CN15: C42.2 J9.A81(PER15N)
PEX_TX_CP0: C8.2 J9.A16(PER0P)
PEX_TX_CP1: C10.2 J9.A21(PER1P)
PEX_TX_CP2: C12.2 J9.A25(PER2P)
PEX_TX_CP3: C14.2 J9.A29(PER3P)
PEX_TX_CP4: C19.2 J9.A35(PER4P)
PEX_TX_CP5: C21.2 J9.A39(PER5P)
PEX_TX_CP6: C23.2 J9.A43(PER6P)
PEX_TX_CP7: C25.2 J9.A47(PER7P)
PEX_TX_CP8: C27.2 J9.A52(PER8P)
PEX_TX_CP9: C29.2 J9.A56(PER9P)
PEX_TX_CP10: C31.2 J9.A60(PER10P)
PEX_TX_CP11: C33.2 J9.A64(PER11P)
PEX_TX_CP12: C35.2 J9.A68(PER12P)
PEX_TX_CP13: C37.2 J9.A72(PER13P)
PEX_TX_CP14: C39.2 J9.A76(PER14P)
PEX_TX_CP15: C41.2 J9.A80(PER15P)
PGM_CONFIG: U11.D12(DIFFIO_T17P) ; also on sheet 29
PGM_LED0: U11.B14(DIFFIO_T17N) ; also on sheet 29
PGM_LED1: U11.C13(DIFFIO_T18P) ; also on sheet 29
PGM_LED2: U11.B16(DIFFIO_T18N) ; also on sheet 29
PGM_SEL: U11.B13(DIFFIO_T16N) ; also on sheet 29
QSPI_SS0_MSEL0: U11.R16(DIFFIO_B22P) ; also on sheet 6
REFCLK1_N: C67.2 ; also on sheet 11
REFCLK1_P: C65.2 ; also on sheet 11
REFCLK4_N: C76.2 ; also on sheet 13
REFCLK4_P: C75.2 ; also on sheet 13
REFCLK_DP_N: C80.2 ; also on sheet 11
REFCLK_DP_P: C79.2 ; also on sheet 11
REFCLK_FMCA_N: C804.2 ; also on sheet 13
REFCLK_FMCA_P: C803.2 ; also on sheet 13
REFCLK_QSFP1_N: C68.2 ; also on sheet 12
REFCLK_QSFP1_P: C66.2 ; also on sheet 12
REFCLK_SDI_N: C86.2 ; also on sheet 12
REFCLK_SDI_P: C85.2 ; also on sheet 12
S10_VCC: U1.P28(VCC) ; also on sheet 15 31 35 36 37 45
S10_VCCH_GXBL: U1.R28(VCCA_PLL) ; also on sheet 15 45
SDI_CLK148_DOWN: R69.1 ; also on sheet 10
SDI_CLK148_UP: R67.1 ; also on sheet 10
SDI_MF0_BYPASS: U11.N9(IOB4_30) ; also on sheet 7 28
SDI_MF1_AUTO_SLEEP: U11.R4(IOB4_31) ; also on sheet 7 28
SDI_MF2_MUTE: U11.M12(IOB4_29) ; also on sheet 7 28
SDI_TX_SD_HDn: U11.T10(IOB4_32) ; also on sheet 7 28
SI516_FS: U11.D7(DIFFIO_T5N) X1.2(FS(OE)) ; also on sheet 28 29
TSENSE_ALERTn: U85.C4(IO_VCC4) ; also on sheet 32
TSENSE_ALERTn_1.8V: U11.T15(DIFFIO_B21N) U85.A4(IO_VL4) ; also on sheet 10
USB_CFG0: U11.M4(DIFFIO_L19N) ; also on sheet 30
USB_CFG1: U11.M3(DIFFIO_L20N) ; also on sheet 30
USB_CFG2: U11.K2(DIFFIO_L14N) ; also on sheet 30
USB_CFG3: U11.K5(DIFFIO_L15P) ; also on sheet 30
USB_CFG4: U11.L1(DIFFIO_L15N) ; also on sheet 30
USB_CFG5: U11.L2(DIFFIO_L16P) ; also on sheet 30
USB_CFG6: U11.K3(DIFFIO_L16N) ; also on sheet 30
USB_CFG7: U11.M2(DIFFIO_L17N) ; also on sheet 30
USB_CFG8: U11.L4(DIFFIO_L18P) ; also on sheet 30
USB_CFG9: U11.L3(DIFFIO_L18N) ; also on sheet 30
USB_CFG10: U11.N1(DIFFIO_L19P) ; also on sheet 30
USB_CFG11: U11.N2(DIFFIO_L20P) ; also on sheet 30
USB_CFG12: U11.M1(DIFFIO_L17P) ; also on sheet 30
USB_CFG13: U11.N3(DIFFIO_L21P) ; also on sheet 30
USB_CFG14: U11.P2(DIFFIO_L21N) ; also on sheet 30
USB_MAX5_CLK: U11.H5(IOB1/CLK0) ; also on sheet 30
N19282899: C98.2 R67.2 R68.1 R69.2 R70.1 X1.1(VC)
N19282976: C85.1 X1.4(CLK+)
N19282979: C86.1 X1.5(CLK-)
N19283079: C99.1 R70.2
N19288375: C94.1 U9.2(CLKIN_N) Y3.1
N19288394: C87.1 U9.1(CLKIN_P) Y3.3
N19288396: R71.1 U9.8(INTR)
N19288755: C809.1 U9.21(CLK0B)
N19288766: C810.1 U9.22(CLK0A)
N20104985: R72.1 U11.J2(DIFFIO_L12N)
N20111728: J9.A6(JTAG_TDI) J9.A7(JTAG_TDO)
N21206886: R58.2 U9.10(CLK3A)
N21206895: R57.2 U9.9(CLK3B)
N21208022: C53.1 C54.1 C55.1 C56.1 C57.1 C58.2 L3.1 U7.22(VDDO0) U7.26(VDDO1) U7.29(VDDO2) U7.33(VDDO3) U7.36(VDDO4) U7.40(VDDO5) U7.43(VDDO6) U7.49(VDDO7) U7.52(VDDO8) U7.57(VDDO9)
N21208054: C52.2 L2.2 U7.13(VDDA)
N21208064: R55.1 U7.6(~{RST})
N21208225: R65.2 U7.39(I2C_SEL)
N21208352: C51.2 L6.2 U7.32(VDD1) U7.46(VDD2) U7.60(VDD3)
N21208406: U7.8(XA) Y1.3
N21208432: U7.9(XB) Y1.1
N21208440: U7.7(X1) Y1.2
N21208444: U7.10(X2) Y1.4
N21208520: C65.1 U7.24(OUT0)
N21208526: C67.1 U7.23(~{OUT0})
N21208560: C66.1 U7.28(OUT1)
N21208566: C68.1 U7.27(~{OUT1})
N21208594: C79.1 U7.31(OUT2)
N21208600: C80.1 U7.30(~{OUT2})
N21208635: C75.1 U7.38(OUT4)
N21208647: C76.1 U7.37(~{OUT4})
N21208672: C803.1 U7.42(OUT5)
N21208684: C804.1 U7.41(~{OUT5})
N21208707: R60.2 U7.54(OUT8)
N21208711: R61.2 U7.53(~{OUT8})
N21208781: R64.2 U7.59(OUT9)
N21208788: U7.58(~{OUT9}) V3.1(TP)
N22772576: Q30.3(COLLECTOR) R5395.1 R5397.1 U85.C3(IO_VCC3)
N22776205: Q30.2(BASE) Q31.3(COLLECTOR) R5398.1

Not connected (* = marked no-connect by the designer): J9 A5(JTAG_TCK)* A8(JTAG_TMS)* A19(RSVD2)* A32(RSVD4)* A33(RSVD5)* A50(RSVD7)* B9(JTAG_TRSTN)* B12(RSVD1)* B30(RSVD3)* B82(RSVD6)*; U5 5(NC)*; U6 A4(IO_VL4)* C4(IO_VCC4)*; U7 5(~{SYNC})* 12(~{INTR})* 20(RSVD1)* 21(RSVD2)* 34(~{OUT3})* 35(OUT3)* 44(~{OUT6})* 45(OUT6)* 47(~{LOL})* 55(RSVD3)* 56(RSVD4)* 61(FB_IN)* 62(~{FB_IN})*; U9 5(FDBK_P)*; U11 A5(DIFFIO_T5P)* A7(DIFFIO_T8N)* A8(DIFFIO_T9N)* A9(DIFFIO_T10P)* A11(DIFFIO_T13N)* A12(DIFFIO_T14N)* A13(IOB2_6)* A15(IOB2_7)* B1(DIFFIO_T1N)* B3(IOB2_12)* B4(DIFFIO_T3P)* B5(DIFFIO_T4N)* B6(DIFFIO_T6P)* B8(DIFFIO_T9P)* B10(IOB2_11)* B11(DIFFIO_T14P)* C2(DIFFIO_L1N)* C3(DIFFIO_L2P)* C4(DIFFIO_T2N)* C5(DIFFIO_T2P)* C6(IOB2_15)* C7(IOB2_16)* C8(DIFFIO_T7P)* C9(DIFFIO_T12N)* C10(IOB2_13)* C12(IOB2_14)* D1(DIFFIO_L4P)* D2(DIFFIO_L3P)* D3(DIFFIO_L1P)* D5(IOB2_19)* D6(DIFFIO_T3N)* D8(DIFFIO_T8P)* D9(DIFFIO_T11N)* D10(IOB2_17)* D11(IOB2_18)* E1(DIFFIO_L5N)* E3(DIFFIO_L2N)* E4(DIFFIO_L3N)* E5(DIFFIO_L4N)* E6(DIFFIO_T4P)* E7(DIFFIO_T6N)* E8(IOB2_20)* E9(DIFFIO_T10N)* E10(DIFFIO_T13P)* F1(DIFFIO_L7P)* F2(DIFFIO_L6N)* F3(DIFFIO_L5P)* F4(DIFFIO_L6P)* F6(DIFFIO_L7N)* F12(IOB3_24)* G2(DIFFIO_L8P)* G3(DIFFIO_L8N)* G4(DIFFIO_L9N)* J3(DIFFIO_L14P)* L5(IOB1_5)* M8(DIFFIO_B13P/DEV_OE)* M9(DIFFIO_B13N/DEV_CLRn)* N8(DIFFIO_B10P)* P8(DIFFIO_B9P)* P9(DIFFIO_B12N)* P11(DIFFIO_B18N)* R8(DIFFIO_B10N)* R9(DIFFIO_B12P)* R13(DIFFIO_B19N)* T7(DIFFIO_B9N)* T8(DIFFIO_B11P)* T9(DIFFIO_B11N)* T13(DIFFIO_B19P)*; U85 A1(IO_VL1)* A2(IO_VL2)* C1(IO_VCC1)* C2(IO_VCC2)*

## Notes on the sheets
sheet 16
- S10 GX Ground
sheet 17
- PCIe Edge x16 Gold Fingers
- Link Width DIP Switch
- H = 0.40mm
  Place on Bottom side
- H = 0.33mm
  Place on Bottom side
sheet 18
- Board System Clocks
- 155.52MHz (LVDS)
- 50MHz(LVCMOS)
- 133MHz (LVDS)
- 100MHz (LVDS)
- 644.53125M (LVDS)
- 100MHz (LVDS)
- Si5338 Programmable Oscillator Use Clock Control GUI
  (Defaults CLK[0:3] =  100MHz, 100MHz, 133MHz, 50MHz
  I2C Address 70 HEX
- 135MHz (LVDS)
- I2C Address = 71h
- 156.25MHz (LVDS)
- 625MHz (LVDS)
- 125MHz (LVDS)
- From FPGA
- 125MHz (LVCMOS)
- Populated with Si516.
  FS Control on DIPSWITCH
  FS=0: 148.35MHz
  FS=1: 148.50MHz
  I2C only available if Si571 is populated.
- 125MHz (LVCMOS)
- I2C Address = 74h
sheet 19
- Max V System Controller
- AVST_READY must be
  double registered
  inside MAXV for
  syncronization to
  AVST_CLK
- H = 1.45mm
  Place on Bottom side
- ON-BOARD USB BLASTER II
- MAXV DIPSWITCH
- PUSH BUTTON INTERFACE
- LED INTERFACE
- VCCINT
- 1.8V VCCIO
- 1.8V VCCIO
- 2.5V VCCIO
